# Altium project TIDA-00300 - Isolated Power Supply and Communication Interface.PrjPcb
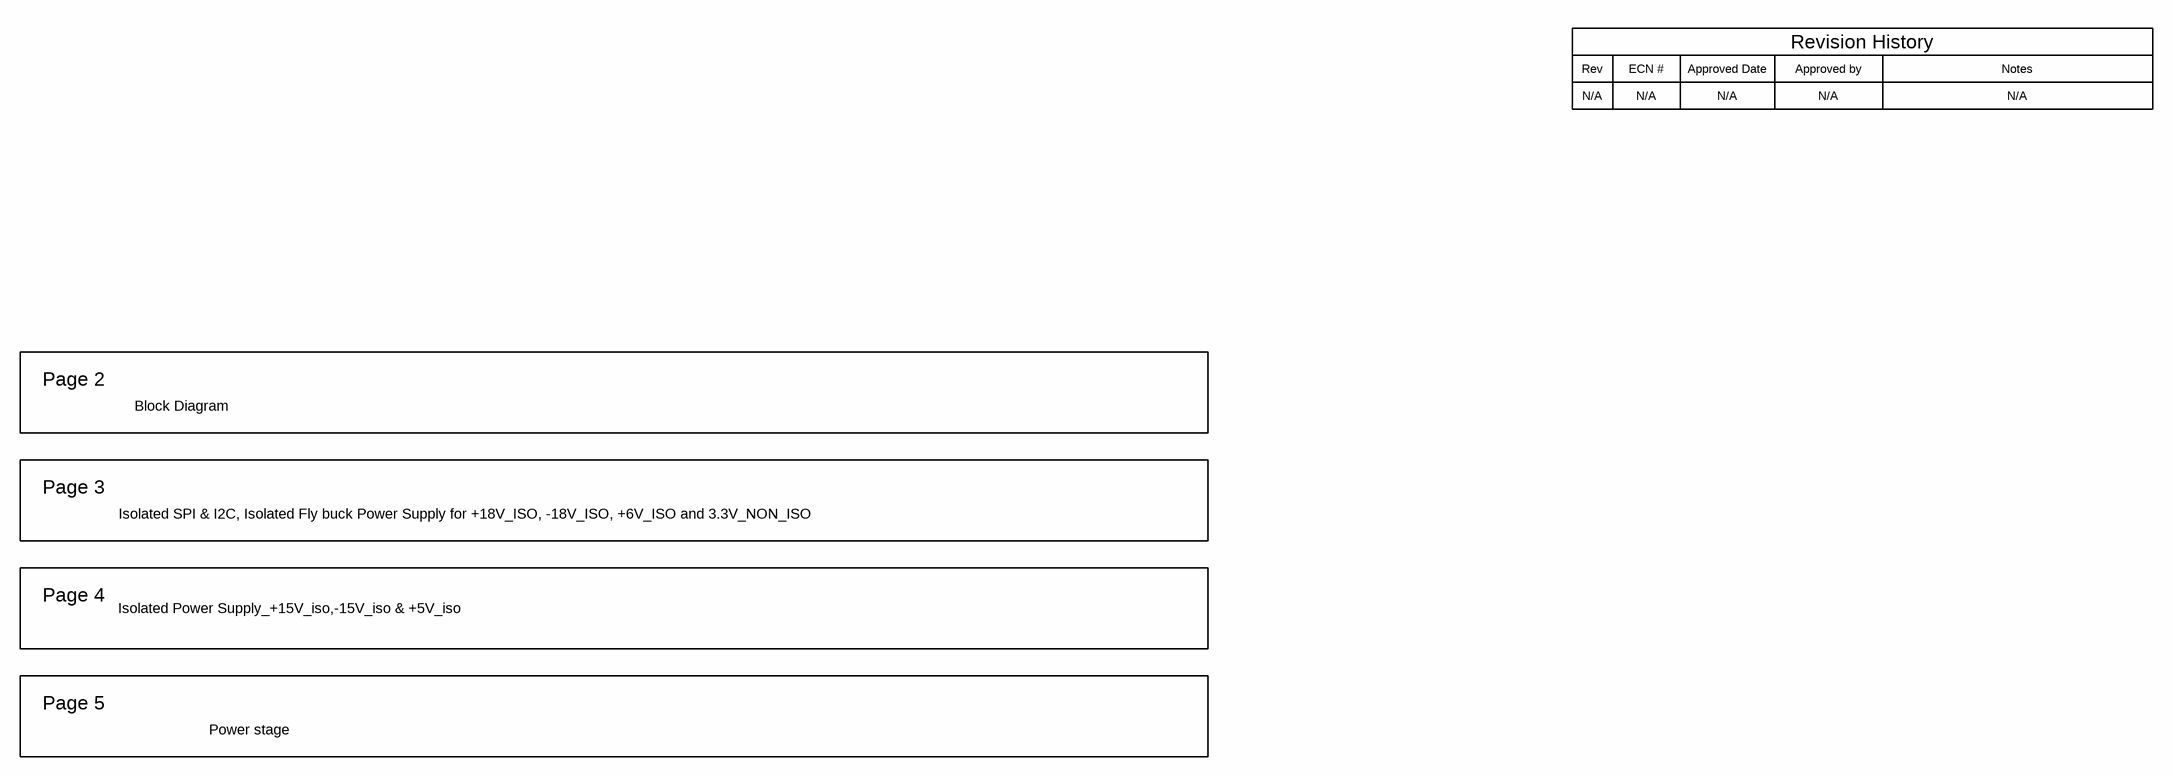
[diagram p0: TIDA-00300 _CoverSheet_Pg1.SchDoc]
CopyrightYear: 2019; PCB_Layout: Avinash N; PCB_Rev: E3; PRJ_Customer: Public Release; PRJ_Engineer: Sreenivasa; PRJ_Number: TIDA-00300; PRJ_Title: Isolated Power Supply and Communication Interface; SCH_Rev: E3; TechSupport: http://www.ti.com/support; TID: 00300
6 sheets, 197 parts. Net scope: flat (ports and power ports of the same name join across sheets).
Board file: TIDA-00300.PcbDoc
Sheets:
  TIDA-00300 _CoverSheet_Pg1.SchDoc
  TIDA-00300 _ Block Diagram_Pg2.SchDoc
  TIDA-00300_Isolated SPI, I2C & Fly buck Power Supply_Pg3 .SchDoc
  TIDA-00300_Isolated Power Supply +15V,-15V & +5V_Pg4 .SchDoc
  TIDA-00300_Power Stage_Pg5.SchDoc
  TIDA-00300_EVM_Hardware_Pg6.SchDoc

## Sheet TIDA-00300 _CoverSheet_Pg1.SchDoc: Coversheet
size 431 x 279 mm; Date: Not shown in title block; ApprovedBy: Not shown in title block; CheckedBy: Not shown in title block; Author: Not shown in title block; CompanyName: Not shown in title block; DrawnBy: Sreenivasa; Engineer: Not shown in title block; Organization: Not shown in title block; Address1: Not shown in title block; Address2: Not shown in title block; Address3: Not shown in title block; Address4: Not shown in title block; DocumentNumber: 1; Revision: Use project parameter SCH_Rev; SheetNumber: 1; SheetTotal: 6; PageSetup: Record=PageOptions¦CenterHorizontal=True¦CenterVertical=True¦PrintScale=1.00¦XCorrection=1.00¦YCorrection=1.00¦PrintKind=0¦BorderSize=5000000¦LeftOffset=0¦BottomOffset=0¦Orientation=2¦PaperLength=1000¦PaperWidth=1000¦Scale=100¦PaperSource=15¦PrintQuality=600¦MediaType=1¦DitherType=10¦PaperKind=Letter¦PrintScaleMode=1

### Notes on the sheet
- Rev
- N/A
- ECN #
- Approved Date
- Approved by
- Revision History
- Notes
- Page 2
- Block Diagram
- Page 3
- Isolated SPI & I2C, Isolated Fly buck Power Supply for +18V_ISO, -18V_ISO, +6V_ISO and 3.3V_NON_ISO
- Page 4
- Isolated Power Supply_+15V_iso,-15V_iso & +5V_iso
- Page 5
- Power stage

## Sheet TIDA-00300 _ Block Diagram_Pg2.SchDoc: Block Diagram
size 431 x 279 mm; Date: Not shown in title block; ApprovedBy: Not shown in title block; CheckedBy: Not shown in title block; Author: Not shown in title block; CompanyName: Not shown in title block; DrawnBy: Sreenivasa; Engineer: Sreenivasa; Organization: Not shown in title block; Address1: Not shown in title block; Address2: Not shown in title block; Address3: Not shown in title block; Address4: Not shown in title block; DocumentNumber: 1; Revision: Use project parameter SCH_Rev; SheetNumber: 2; SheetTotal: 6; PageSetup: Record=PageOptions¦CenterHorizontal=True¦CenterVertical=True¦PrintScale=1.00¦XCorrection=1.00¦YCorrection=1.00¦PrintKind=0¦BorderSize=5000000¦LeftOffset=0¦BottomOffset=0¦Orientation=2¦PaperLength=1000¦PaperWidth=1000¦Scale=100¦PaperSource=15¦PrintQuality=600¦MediaType=1¦DitherType=10¦PaperKind=Letter¦PrintScaleMode=1
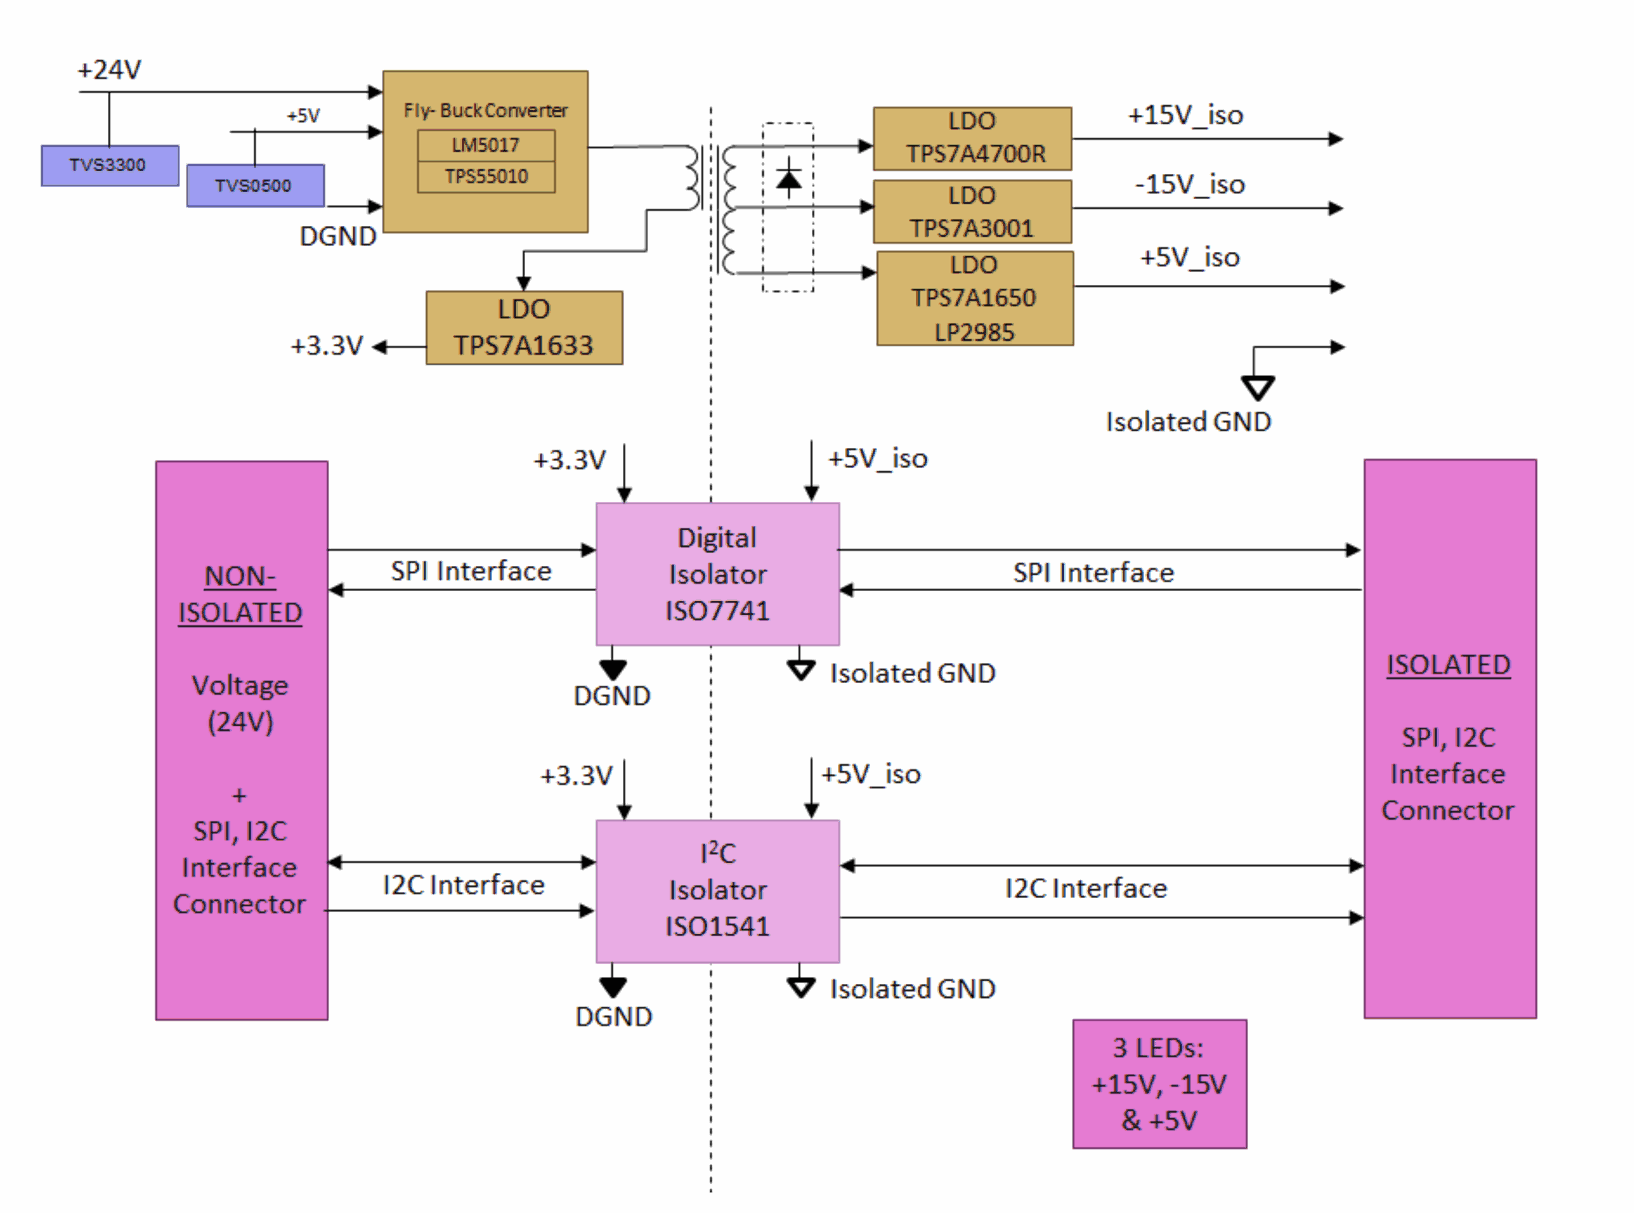
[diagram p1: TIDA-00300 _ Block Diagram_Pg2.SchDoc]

## Sheet TIDA-00300_Isolated SPI, I2C & Fly buck Power Supply_Pg3 .SchDoc
size 431 x 279 mm; Date: Not shown in title block; ApprovedBy: Not shown in title block; CheckedBy: Not shown in title block; Author: Not shown in title block; CompanyName: Not shown in title block; DrawnBy: Sreenivasa; Engineer: Not shown in title block; Organization: Not shown in title block; Address1: Not shown in title block; Address2: Not shown in title block; Address3: Not shown in title block; Address4: Not shown in title block; DocumentNumber: 1; Revision: Use project parameter SCH_Rev; SheetNumber: 3; SheetTotal: 6; PageSetup: Record=PageOptions¦CenterHorizontal=True¦CenterVertical=True¦PrintScale=0.62¦XCorrection=1.00¦YCorrection=1.00¦PrintKind=0¦BorderSize=5000000¦LeftOffset=0¦BottomOffset=0¦Orientation=2¦PaperLength=1000¦PaperWidth=1000¦Scale=100¦PaperSource=15¦PrintQuality=600¦MediaType=1¦DitherType=10¦PrintScaleMode=1¦PaperKind=Letter
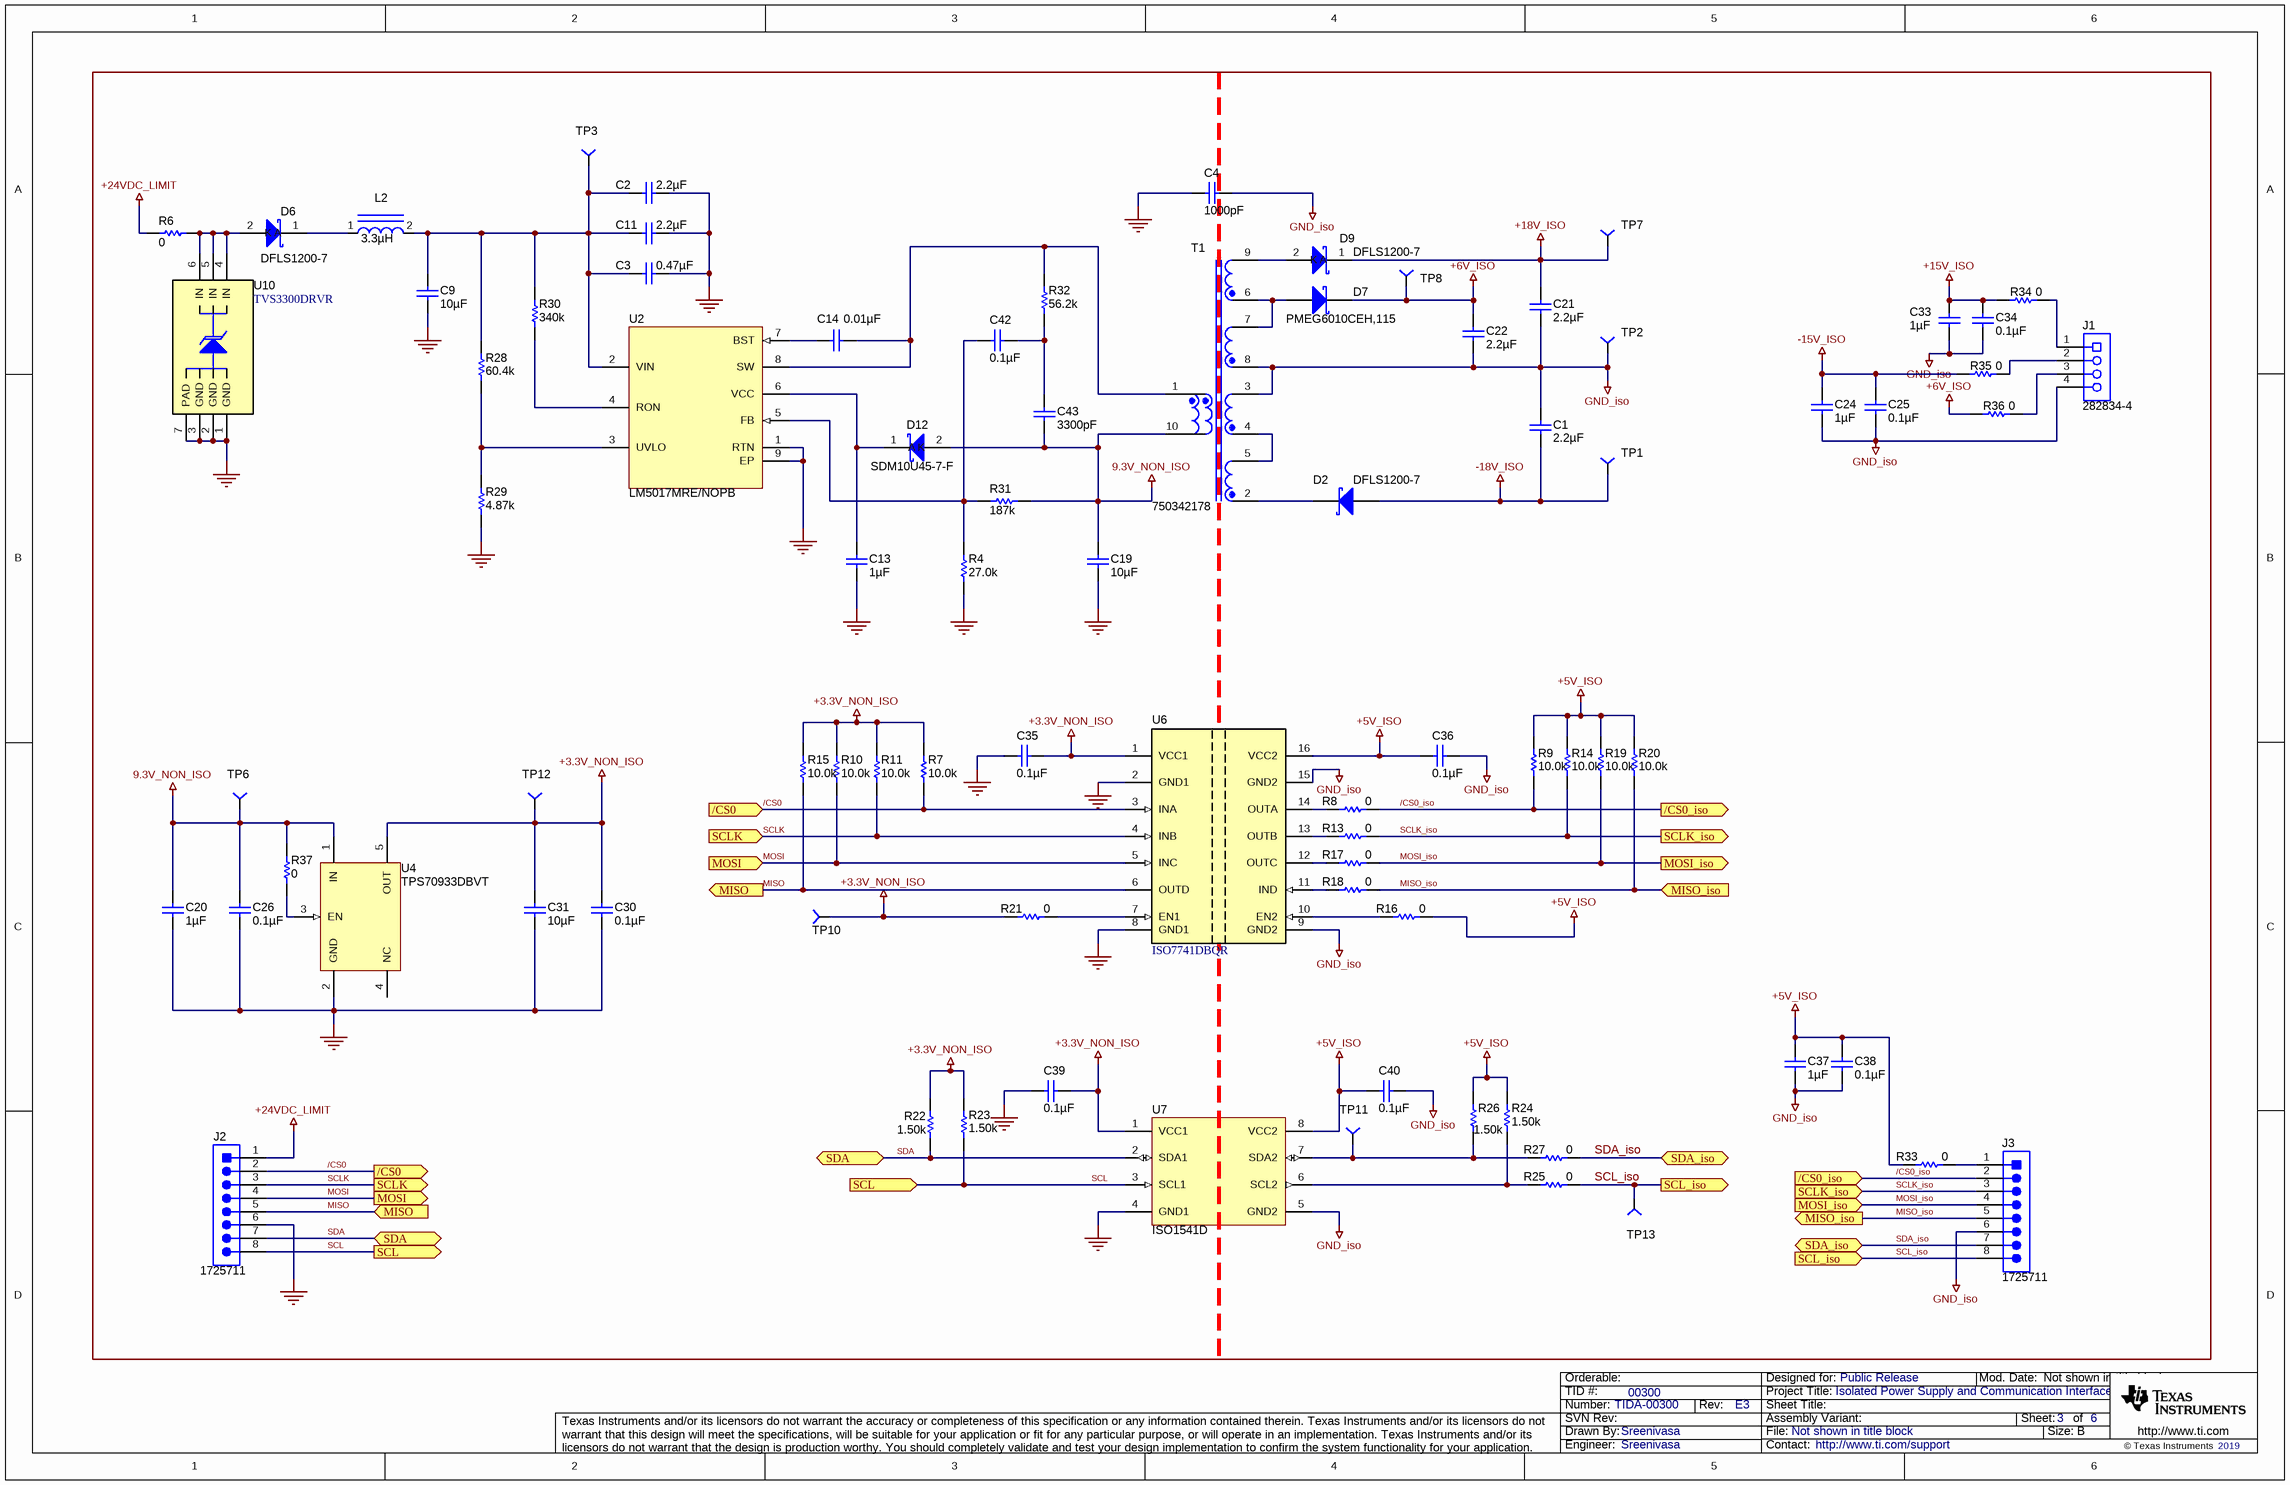
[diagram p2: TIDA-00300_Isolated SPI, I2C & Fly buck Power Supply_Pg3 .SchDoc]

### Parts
C1  ValueDisplayed: 2.2µF  [0805_HV]  (hidden comment: GRM21BR71E225KA73L)
C2  ValueDisplayed: 2.2µF  [1210]  (hidden comment: GRM32ER72A225KA35L)
C3  ValueDisplayed: 0.47µF  [1206]  (hidden comment: ESD61C474K4T2A-28)
C4  ValueDisplayed: 1000pF  [1812]  (hidden comment: 1812GC102KAT1A)
C9  ValueDisplayed: 10µF  [1210]  (hidden comment: GRM32ER71H106KA12L)
C11  ValueDisplayed: 2.2µF  [1210]  (hidden comment: GRM32ER72A225KA35L)
C13  ValueDisplayed: 1µF  [0603]  (hidden comment: C1608X5R1H105K080AB)
C14  ValueDisplayed: 0.01µF  [0603]  (hidden comment: 06031C103JAT2A)
C19  ValueDisplayed: 10µF  [1210]  (hidden comment: GMK325AB7106MM-T)
C20  ValueDisplayed: 1µF  [0805]  (hidden comment: 08055C105KAT2A)
C21  ValueDisplayed: 2.2µF  [0805_HV]  (hidden comment: GRM21BR71E225KA73L)
C22  ValueDisplayed: 2.2µF  [0805_HV]  (hidden comment: GRM21BR71E225KA73L)
C24  ValueDisplayed: 1µF  [0603]  (hidden comment: C1608X5R1H105K080AB)
C25  ValueDisplayed: 0.1µF  [0603]  (hidden comment: GRM188R72A104KA35D)
C26  ValueDisplayed: 0.1µF  [0603]  (hidden comment: C0603C104K5RACTU)
C30  ValueDisplayed: 0.1µF  [0603]  (hidden comment: C0603C104K5RACTU)
C31  ValueDisplayed: 10µF  [0805]  (hidden comment: 0805YD106MAT2A)
C33  ValueDisplayed: 1µF  [0603]  (hidden comment: C1608X5R1H105K080AB)
C34  ValueDisplayed: 0.1µF  [0603]  (hidden comment: GRM188R72A104KA35D)
C35  ValueDisplayed: 0.1µF  [0603]  (hidden comment: C0603C104K5RACTU)
C36  ValueDisplayed: 0.1µF  [0603]  (hidden comment: C0603C104K5RACTU)
C37  ValueDisplayed: 1µF  [0603]  (hidden comment: C1608X5R1H105K080AB)
C38  ValueDisplayed: 0.1µF  [0603]  (hidden comment: GRM188R72A104KA35D)
C39  ValueDisplayed: 0.1µF  [0603]  (hidden comment: C0603C104K5RACTU)
C40  ValueDisplayed: 0.1µF  [0603]  (hidden comment: C0603C104K5RACTU)
C42  ValueDisplayed: 0.1µF  [0603]  (hidden comment: GRM188R72A104KA35D)
C43  ValueDisplayed: 3300pF  [0603]  (hidden comment: 06031C332JAT2A)
D2  DFLS1200-7  [powerDI123]
D6  DFLS1200-7  [powerDI123]
D7  PMEG6010CEH,115  [SOD-123F]
D9  DFLS1200-7  [powerDI123]
D12  SDM10U45-7-F  [SOD-523]
J1  282834-4  [TEC_282834-4]
J2  1725711  [CONN_1725711]
J3  1725711  [CONN_1725711]
L2  3.3µH  [IND_B82422H]
R4  value 27.0k  [0603]  (hidden comment: RC0603FR-0727KL)
R6  value 0  [1206]  (hidden comment: RC1206JR-070RL)
R7  value 10.0k  [0603]  (hidden comment: CRCW060310K0FKEA)
R8  value 0  [0603]  (hidden comment: RC0603JR-070RL)
R9  value 10.0k  [0603]  (hidden comment: CRCW060310K0FKEA)
R10  value 10.0k  [0603]  (hidden comment: CRCW060310K0FKEA)
R11  value 10.0k  [0603]  (hidden comment: CRCW060310K0FKEA)
R13  value 0  [0603]  (hidden comment: RC0603JR-070RL)
R14  value 10.0k  [0603]  (hidden comment: CRCW060310K0FKEA)
R15  value 10.0k  [0603]  (hidden comment: CRCW060310K0FKEA)
R16  value 0  [0603]  (hidden comment: RC0603JR-070RL)
R17  value 0  [0603]  (hidden comment: RC0603JR-070RL)
R18  value 0  [0603]  (hidden comment: RC0603JR-070RL)
R19  value 10.0k  [0603]  (hidden comment: CRCW060310K0FKEA)
R20  value 10.0k  [0603]  (hidden comment: CRCW060310K0FKEA)
R21  value 0  [0603]  (hidden comment: RC0603JR-070RL)
R22  value 1.50k  [0603]  (hidden comment: CRCW06031K50FKEA)
R23  value 1.50k  [0603]  (hidden comment: CRCW06031K50FKEA)
R24  value 1.50k  [0603]  (hidden comment: CRCW06031K50FKEA)
R25  value 0  [0603]  (hidden comment: RC0603JR-070RL)
R26  value 1.50k  [0603]  (hidden comment: CRCW06031K50FKEA)
R27  value 0  [0603]  (hidden comment: RC0603JR-070RL)
R28  value 60.4k  [0603]  (hidden comment: ERA-3AEB6042V)
R29  value 4.87k  [0603]  (hidden comment: RC0603FR-074K87L)
R30  value 340k  [0603]  (hidden comment: CRCW0603340KFKEA)
R31  value 187k  [0603]  (hidden comment: ERA-3AEB1873V)
R32  value 56.2k  [0603]  (hidden comment: ERA-3AEB5622V)
R33  value 0  [1206]  (hidden comment: RC1206JR-070RL)
R34  value 0  [1206]  (hidden comment: RC1206JR-070RL)
R35  value 0  [1206]  (hidden comment: RC1206JR-070RL)
R36  value 0  [1206]  (hidden comment: RC1206JR-070RL)
R37  value 0  [0603]  (hidden comment: RC0603JR-070RL)
T1  750342178  [WURTH_750313995]
TP1  TP1_PD40_D0.5_S50  [TP1_PD40_D0.5_S50]  (value not drawn)
TP2  TP1_PD40_D0.5_S50  [TP1_PD40_D0.5_S50]  (value not drawn)
TP3  TP1_PD40_D0.5_S50  [TP1_PD40_D0.5_S50]  (value not drawn)
TP6  TP1_PD40_D0.5_S50  [TP1_PD40_D0.5_S50]  (value not drawn)
TP7  TP1_PD40_D0.5_S50  [TP1_PD40_D0.5_S50]  (value not drawn)
TP8  TP1_PD40_D0.5_S50  [TP1_PD40_D0.5_S50]  (value not drawn)
TP10  TP1_PD40_D0.5_S50  [TP1_PD40_D0.5_S50]  (value not drawn)
TP11  TP1_PD40_D0.5_S50  [TP1_PD40_D0.5_S50]  (value not drawn)
TP12  TP1_PD40_D0.5_S50  [TP1_PD40_D0.5_S50]  (value not drawn)
TP13  TP1_PD40_D0.5_S50  [TP1_PD40_D0.5_S50]  (value not drawn)
U2  LM5017MRE/NOPB  [DDA0008B_N]
U4  TPS70933DBVT  [DBV0005A_N]
U6  ISO7741DBQR  [DBQ0016A_N]
U7  ISO1541D  [D0008A_N]
U10  TVS3300DRVR  [DRV0006A]

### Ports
/CS0 (in), /CS0 (out), /CS0_iso (in), /CS0_iso (out), MISO (in), MISO (out), MISO_iso (in), MISO_iso (out), MOSI (in), MOSI (out), MOSI_iso (in), MOSI_iso (out), SCL (in), SCL (out), SCL_iso (in), SCL_iso (out), SCLK (in), SCLK (out), SCLK_iso (in), SCLK_iso (out), SDA (bidir), SDA_iso (bidir)

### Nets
9.3V_NON_ISO: C19.1 C20.1 C26.1 C43.2 D12.2(A) R31.2 R37.2 T1.10 TP6.1 U4.1(IN)
+3.3V_NON_ISO: C30.1 C31.1 C35.2 C39.2 R7.2 R10.2 R11.2 R15.2 R21.1 R22.2 R23.2 TP10.1 TP12.1 U4.5(OUT) U6.1(VCC1) U7.1(VCC1)
+5V_ISO: C36.1 C37.1 C38.2 C40.1 R9.2 R14.2 R16.2 R19.2 R20.2 R24.2 R26.2 R33.1 U6.16(VCC2) U7.8(VCC2)
+6V_ISO: C22.1 D7.1(K) R36.1 TP8.1
+15V_ISO: C33.2 C34.2 R34.1
+18V_ISO: C21.1 D9.1(K) TP7.1
+24VDC_LIMIT: J2.1 R6.2
-15V_ISO: C24.1 C25.2 R35.1
-18V_ISO: C1.2 D2.2(A) TP1.1
GND: C2.1 C3.1 C4.2 C9.2 C11.1 C13.2 C19.2 C20.2 C26.2 C30.2 C31.2 C35.1 C39.1 J2.6 R4.1 R29.1 U2.1(RTN) U2.9(EP) U4.2(GND) U6.2(GND1) U6.8(GND1) U7.4(GND1) U10.1(GND) U10.2(GND) U10.3(GND) U10.7(PAD)
GND_iso: C1.1 C4.1 C21.2 C22.2 C24.2 C25.1 C33.1 C34.1 C36.2 C37.2 C38.1 C40.2 J1.4 J3.6 T1.3 T1.8 TP2.1 U6.9(GND2) U6.15(GND2) U7.5(GND2)
/CS0: J2.2 R7.1 U6.3(INA) ; port /CS0
/CS0_iso: J3.2 R8.2 R9.1 ; port /CS0_iso
MISO: J2.5 R15.1 U6.6(OUTD) ; port MISO
MISO_iso: J3.5 R18.2 R20.1 ; port MISO_iso
MOSI: J2.4 R10.1 U6.5(INC) ; port MOSI
MOSI_iso: J3.4 R17.2 R19.1 ; port MOSI_iso
SCL: J2.8 R23.1 U7.3(SCL1) ; port SCL
SCL_iso: J3.8 R25.2 TP13.1 ; port SCL_iso
SCLK: J2.3 R11.1 U6.4(INB) ; port SCLK
SCLK_iso: J3.3 R13.2 R14.1 ; port SCLK_iso
SDA: J2.7 R22.1 U7.2(SDA1) ; port SDA
SDA_iso: J3.7 R27.2 ; port SDA_iso
NetC2_2: C2.2 C3.2 C9.1 C11.2 L2.2 R28.2 R30.2 TP3.1 U2.2(VIN)
NetC13_1: C13.1 D12.1(K) U2.6(VCC)
NetC14_1: C14.1 U2.7(BST)
NetC14_2: C14.2 R32.2 T1.1 U2.8(SW)
NetC42_1: C42.1 C43.1 R32.1
NetC42_2: C42.2 R4.2 R31.1 U2.5(FB)
NetD2_1: D2.1(K) T1.2
NetD6_1: D6.1(K) L2.1
NetD6_2: D6.2(A) R6.1 U10.4(IN) U10.5(IN) U10.6(IN)
NetD7_2: D7.2(A) T1.6 T1.7
NetD9_2: D9.2(A) T1.9
NetJ1_1: J1.1 R34.2
NetJ1_2: J1.2 R35.2
NetJ1_3: J1.3 R36.2
NetJ3_1: J3.1 R33.2
NetR8_1: R8.1 U6.14(OUTA)
NetR13_1: R13.1 U6.13(OUTB)
NetR16_1: R16.1 U6.10(EN2)
NetR17_1: R17.1 U6.12(OUTC)
NetR18_1: R18.1 U6.11(IND)
NetR21_2: R21.2 U6.7(EN1)
NetR24_1: R24.1 R25.1 U7.6(SCL2)
NetR26_1: R26.1 R27.1 TP11.1 U7.7(SDA2)
NetR28_1: R28.1 R29.2 U2.3(UVLO)
NetR30_1: R30.1 U2.4(RON)
NetR37_1: R37.1 U4.3(EN)
NetT1_4: T1.4 T1.5

Not connected (* = marked no-connect by the designer): U4 4(NC)

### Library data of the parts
C1 C21 C22 = GRM21BR71E225KA73L: CAP, CERM, 2.2uF, 25V, +/-10%, X7R, 0805; Manufacturer: MuRata; Polarized: N; CompType: Capacitor; U/M: EA; Cap_F: 0.0000022; Tolerance_%: 10; ESR_Ohm: 0.005; Value1: 0.005 ohm; VDC_V: 25; TaMin_C: -55; TaMax_C: 125; Cap_Case: 0805
C2 C11 = GRM32ER72A225KA35L: CAP, CERM, 2.2uF, 100V, +/-10%, X7R, 1210; Manufacturer: MuRata; Polarized: N; CompType: Capacitor; U/M: EA; Cap_F: 0.0000022; Tolerance_%: 10; ESR_Ohm: 0.007; Value1: 0.007 ohm; VDC_V: 100; IRMS_A: 4.4; TaMin_C: -55; TaMax_C: 125
C3 = GRM31MR72A474KA35L: CAP, CERM, 0.47uF, 100V, +/-10%, X7R, 1206; Manufacturer: AVX Corporation; Polarized: N; CompType: Capacitor; U/M: EA; Cap_F: 0.00000047; Tolerance_%: 10; Value1: Unknown; VDC_V: 100; TaMin_C: -55; TaMax_C: 125
C4 = 1812GC102KA1: CAP, CERM, 1000pF, 2000V, +/-10%, X7R, 1812; Manufacturer: AVX; Polarized: N; CompType: Capacitor; U/M: EA; Cap_F: 0.000000001; Tolerance_%: 10; Value1: Unknown; VDC_V: 2000; TaMin_C: -55; TaMax_C: 125
C9 = GRM32ER71H106KA12L: CAP, CERM, 10uF, 50V, +/-10%, X7R, 1210; Manufacturer: MuRata; Polarized: N; CompType: Capacitor; U/M: EA; Cap_F: 0.00001; Tolerance_%: 10; Value1: Unknown; VDC_V: 50; TaMin_C: -55; TaMax_C: 125
C13 C24 C33 C37 = GRM188R61H105KAALD: CAP, CERM, 1uF, 50V, +/-10%, X5R, 0603; Manufacturer: TDK Corporation; Polarized: N; CompType: Capacitor; U/M: EA; Cap_F: 0.000001; Tolerance_%: 10; Value1: Unknown; VDC_V: 50; TaMin_C: -55; TaMax_C: 85
C14 = 06031C103JAT2A: CAP, CERM, 0.01uF, 100V, +/-5%, X7R, 0603; Manufacturer: AVX; Polarized: N; CompType: Capacitor; U/M: EA; Cap_F: 0.00000001; Tolerance_%: 5; ESR_Ohm: 0.098; Value1: 0.098 ohm; VDC_V: 100; TaMin_C: -55; TaMax_C: 125
C19 = GMK325AB7106MM-T: CAP, CERM, 10uF, 35V, +/-20%, X7R, 1210; Manufacturer: Taiyo Yuden; Polarized: N; CompType: Capacitor; U/M: EA; Cap_F: 0.00001; Tolerance_%: 20; Value1: Unknown; VDC_V: 35; TaMin_C: -55; TaMax_C: 125
C20 = 08055C105KAT2A: CAP, CERM, 1uF, 50V, +/-10%, X7R, 0805; Manufacturer: AVX; Polarized: N; CompType: Capacitor; U/M: EA; Cap_F: 0.000001; Tolerance_%: 10; Value1: Unknown; VDC_V: 50; TaMin_C: -55; TaMax_C: 125
C25 C34 C38 C42 = GRM188R72A104KA35D: CAP, CERM, 0.1uF, 100V, +/-10%, X7R, 0603; Manufacturer: MuRata; Polarized: N; CompType: Capacitor; U/M: EA; Cap_F: 0.0000001; Tolerance_%: 10; Value1: Unknown; VDC_V: 100; TaMin_C: -55; TaMax_C: 125
C26 C30 C35 C36 C39 C40 = C0603C104K5RACTU: CAP, CERM, 0.1uF, 50V, +/-10%, X7R, 0603; Manufacturer: Kemet; Polarized: N; CompType: Capacitor; U/M: EA; Cap_F: 0.0000001; Tolerance_%: 10; Value1: Unknown; VDC_V: 50; TaMin_C: -55; TaMax_C: 125
C31 = 0805YD106MAT2A: CAP, CERM, 10uF, 16V, +/-20%, X5R, 0805; Manufacturer: AVX; Polarized: N; CompType: Capacitor; U/M: EA; Cap_F: 0.00001; Tolerance_%: 20; Value1: Unknown; VDC_V: 16; TaMin_C: -55; TaMax_C: 85
C43 = 06031C332JAT2A: CAP, CERM, 3300pF, 100V, +/-5%, X7R, 0603; Manufacturer: AVX; Polarized: N; CompType: Capacitor; U/M: EA; Cap_F: 0.0000000033; Tolerance_%: 5; ESR_Ohm: 0.159; Value1: 0.159 ohm; VDC_V: 100; TaMin_C: -55; TaMax_C: 125
D2 D6 D9 = DFLS1200-7: Diode, Schottky, 200V, 1A, PowerDI123; Manufacturer: Diodes Inc.; U/M: EA; Vf_V: 0.85; Value2: 0.85V; Io_A: 1; Vr_V: 200; TJmax_C: 175; RJC_CperW: 7
D7 = PMEG6010CEH,115: Diode, Schottky, 60V, 1A, SOD-123F; Manufacturer: NXP Semiconductor; U/M: EA; Vf_V: 0.57; Value2: 0.57V; Io_A: 1; Vr_V: 60; TJmax_C: 150
D12 = SDM10U45-7-F: Diode, Schottky, 45V, 0.1A, SOD-523; Manufacturer: Diodes Inc.; U/M: EA; Vf_V: 0.58; Value2: 0.58V; Io_A: 0.1; Vr_V: 45; TJmax_C: 125
J1 = 282834-4: Receptacle, 100mil, 4X1 TH; Manufacturer: TE Connectivity; SymbolCreator: a0411947; U/M: EA
J2 J3 = 1725711: Terminal Block, 8x1, 2.54 mm, TH; Manufacturer: Phoenix Contact; SymbolCreator: a0411947; U/M: EA
L2 = IND_ELJEA_SERIES: Inductor, Chip, ±10%; Manufacturer: EPCOS INC.; PartNumber: B82422H1332K; Area: 28000
R4 = RC0603FR-0727KL: RES, 27.0k ohm, 1%, 0.1W, 0603; Manufacturer: Yageo America; CompType: Resistor; Res_ohm: 27000; Value_Code: 27k0; Tolerance_%: 1; Power_W: 0.1; VDC_V: 150; TempCo: 200 ppm/C; U/M: EA
R6 = RC0402JR-070RL: RES, 0 ohm,0.1W, 1206; Manufacturer: Yageo America; CompType: Resistor; Value_Code: 0000; Tolerance_%: 5; Power_W: 0.1; VDC_V: 50; TempCo: 200 ppm/C; EIA_Code: E24; U/M: EA
R7 R9-R11 R14 R15 R19 R20 = RG1608P-103-B-T5: RES, 10.0k ohm, 1%, 0.1W, 0603; Manufacturer: Vishay Dale; CompType: Resistor; Res_ohm: 10000; Value_Code: 10k0; Tolerance_%: 1; Power_W: 0.1; VDC_V: 75; TempCo: 25 ppm/C; EIA_Code: E192; U/M: EA
R8 R13 R16-R18 R21 R25 R27 R37 = RC0402JR-070RL: RES, 0 ohm,5%, 0.1W, 0603; Manufacturer: Yageo America; CompType: Resistor; Value_Code: 0000; Tolerance_%: 5; Power_W: 0.1; VDC_V: 50; TempCo: 200 ppm/C; EIA_Code: E24; U/M: EA
R22-R24 R26 = CRCW06031K50FKEA: RES, 1.50k ohm, 1%, 0.1W, 0603; Manufacturer: Vishay-Dale; CompType: Resistor; Res_ohm: 1500; Value_Code: 1k50; Tolerance_%: 1; Power_W: 0.1; VDC_V: 75; TempCo: 100 ppm/C; EIA_Code: E96; U/M: EA
R28 = RT0603BRD0760K4L: RES, 60.4k ohm, 0.1%, 0.1W, 0603; Manufacturer: Panasonic Electronic Components; CompType: Resistor; Res_ohm: 60400; Value_Code: 60k4; Tolerance_%: 0.1; VDC_V: 75; TempCo: 25 ppm/C; EIA_Code: E192; U/M: EA
R29 = RC0603FR-074K87L: RES, 4.87k ohm, 1%, 0.1W, 0603; Manufacturer: Yageo America; CompType: Resistor; Res_ohm: 4870; Value_Code: 4k87; Tolerance_%: 1; Power_W: 0.1; VDC_V: 150; TempCo: 200 ppm/C; EIA_Code: E96; U/M: EA
R30 = RT0603BRD07340KL: RES, 340k ohm,1%, 0.1W, 0603; Manufacturer: Vishay Dale; CompType: Resistor; Res_ohm: 340000; Tolerance_%: 0.1; VDC_V: 75; TempCo: 25 ppm/C; EIA_Code: E192; U/M: EA
R31 = RT0603BRD07189KL: RES 187K OHM 1/10W .1% 0603 SMD; Manufacturer: Panasonic Electronic Components; CompType: Resistor; Res_ohm: 189000; Value_Code: 189k; Tolerance_%: 0.1; Value1: 0.1%; Value2: 0.1W; VDC_V: 75; TempCo: 25 ppm/C; EIA_Code: E192; U/M: EA
R32 = RT0603BRD0756K2L: RES, 56.2k ohm, 0.1%, 0.1W, 0603; Manufacturer: Panasonic Electronic Components; CompType: Resistor; Res_ohm: 56200; Value_Code: 56k2; Tolerance_%: 0.1; VDC_V: 75; TempCo: 25 ppm/C; EIA_Code: E192; U/M: EA
R33-R36 = RC0402JR-070RL: RES, 0 ohm,5%, 0.25W, 1206; Manufacturer: Yageo America; CompType: Resistor; Value_Code: 0000; Tolerance_%: 5; Power_W: 0.1; Value2: 0.125W; VDC_V: 50; TempCo: 200 ppm/C; EIA_Code: E24; U/M: EA
T1 = 750313995: Transformer, 50uH, SMT; Manufacturer: Wurth Elektronik eiSos; SymbolCreator: a0411947; DCR_Ohm: 0.11; LeakageL: 0.130uH; U/M: EA
TP1-TP3 TP6-TP8 TP10-TP13 = TP-040_RND: Test Point 40mil pad 20mil drill; Manufacturer: STD; Value: STD
U2 = LM5017MRE/NOPB: 100V, 600mA Constant On-Time Synchronous Buck Regulator, DDA0008B; Alternate Manufacturer: None; Manufacturer: Texas Instruments; SymbolCreator: a0412235; CompType: IC; U/M: EA
U4 = TPS70933DBVT: IC REG LDO 3.3V 0.15A SOT23-5; Alternate Manufacturer: None; Manufacturer: Texas Instruments; SymbolCreator: a0411947; U/M: EA
U6 = CMP-0013040-1: High Speed, Robust EMC Quad-Channel Digital Isolators, DBQ0016A (SSOP-16); Alternate Manufacturer: Texas Instruments; SizeAreaWB_mm2: 96; U/M: EA; SizeZ_mm: 1.75; SizeX_mm: 6; SizeY_mm: 10; SizeArea_mm2: 60; CompType: IC
U7 = ISO1541D: Low-Power Bidirectional I2C Isolators, D0008A; Alternate Manufacturer: None; Manufacturer: Texas Instruments; SymbolCreator: a0411947; CompType: IC; U/M: EA
U10 = CMP-0013424-7: 33-V Precision Surge Protection Clamp, DRV0006A (WSON-6); Manufacturer: Texas Instruments; Alternate PartNumber: TVS3300DRVT; SizeX_mm: 2; CompType: IC; SizeZ_mm: 0.8; SizeArea_mm2: 4; SizeAreaWB_mm2: 9; U/M: EA

## Sheet TIDA-00300_Isolated Power Supply +15V,-15V & +5V_Pg4 .SchDoc
size 431 x 279 mm; Date: Not shown in title block; ApprovedBy: Not shown in title block; CheckedBy: Not shown in title block; Author: Not shown in title block; CompanyName: Not shown in title block; DrawnBy: Sreenivasa; Engineer: Not shown in title block; Organization: Not shown in title block; Address1: Not shown in title block; Address2: Not shown in title block; Address3: Not shown in title block; Address4: Not shown in title block; DocumentNumber: 1; Revision: Use project parameter SCH_Rev; SheetNumber: 4; SheetTotal: 6; PageSetup: Record=PageOptions¦CenterHorizontal=True¦CenterVertical=True¦PrintScale=0.62¦XCorrection=1.00¦YCorrection=1.00¦PrintKind=0¦BorderSize=5000000¦LeftOffset=0¦BottomOffset=0¦Orientation=2¦PaperLength=1000¦PaperWidth=1000¦Scale=100¦PaperSource=15¦PrintQuality=600¦MediaType=1¦DitherType=10¦PrintScaleMode=1¦PaperKind=Letter
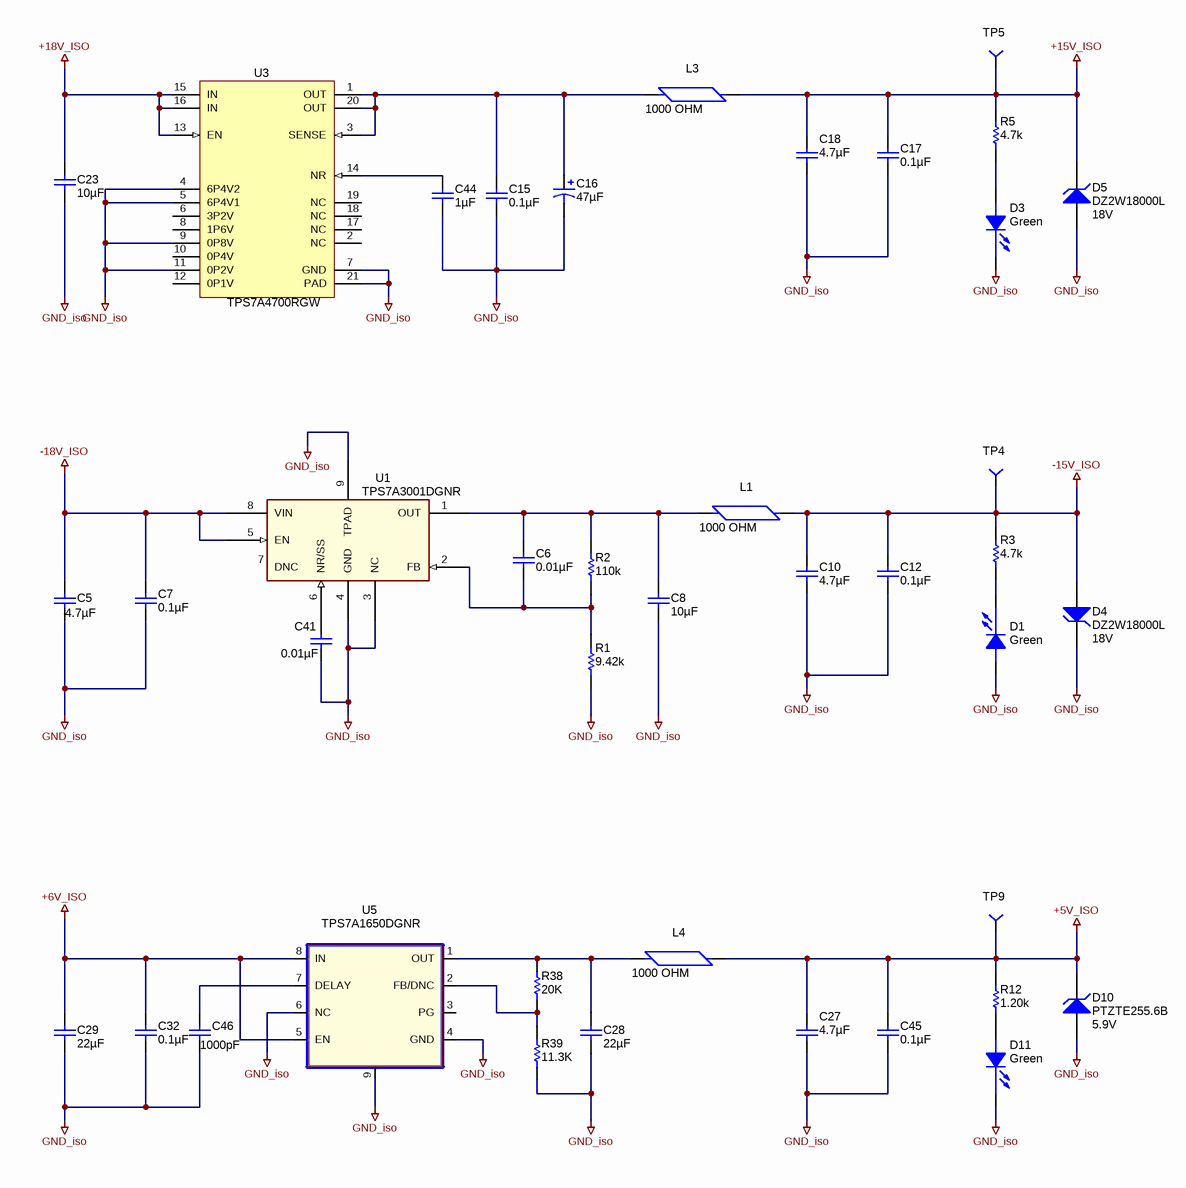
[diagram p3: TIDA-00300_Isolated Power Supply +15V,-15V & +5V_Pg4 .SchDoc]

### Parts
C5  ValueDisplayed: 4.7µF  [1206]  (hidden comment: GRM31CR71H475KA12L)
C6  ValueDisplayed: 0.01µF  [0603]  (hidden comment: 06031C103JAT2A)
C7  ValueDisplayed: 0.1µF  [0603]  (hidden comment: 06035C104KAT2A)
C8  ValueDisplayed: 10µF  [1206]  (hidden comment: GRM31CR71E106KA12L)
C10  ValueDisplayed: 4.7µF  [0805_HV]  (hidden comment: C2012X5R1H475K125AB)
C12  ValueDisplayed: 0.1µF  [0603]  (hidden comment: 06035C104KAT2A)
C15  ValueDisplayed: 0.1µF  [0603]  (hidden comment: 06035C104KAT2A)
C16  ValueDisplayed: 47µF  [7343-43]  (hidden comment: T495X476K035ATE300)
C17  ValueDisplayed: 0.1µF  [0603]  (hidden comment: 06035C104KAT2A)
C18  ValueDisplayed: 4.7µF  [0805_HV]  (hidden comment: C2012X5R1H475K125AB)
C23  ValueDisplayed: 10µF  [1210]  (hidden comment: GRM32ER71H106KA12L)
C27  ValueDisplayed: 4.7µF  [0805_HV]  (hidden comment: C2012X5R1H475K125AB)
C28  ValueDisplayed: 22µF  [0805_HV]  (hidden comment: GRM21BR61C226ME44)
C29  ValueDisplayed: 22µF  [0805_HV]  (hidden comment: GRM21BR61C226ME44)
C32  ValueDisplayed: 0.1µF  [0603]  (hidden comment: 06035C104KAT2A)
C41  ValueDisplayed: 0.01µF  [0603]  (hidden comment: 06031C103JAT2A)
C44  ValueDisplayed: 1µF  [0603]  (hidden comment: C1608X7R1E105K080AB)
C45  ValueDisplayed: 0.1µF  [0603]  (hidden comment: 06035C104KAT2A)
C46  ValueDisplayed: 1000pF  [0603]  (hidden comment: 06031C102JAT2A)
D1  value Green  [LED0603AA]  (hidden comment: LED_LG L29K-G2J1-24-Z)
D3  value Green  [LED0603AA]  (hidden comment: LED_LG L29K-G2J1-24-Z)
D4  DZ2W18000L  value 18V  [SOD-123]
D5  DZ2W18000L  value 18V  [SOD-123]
D10  PTZTE255.6B  value 5.9V  [DIO_SOD-106]
D11  value Green  [LED0603AA]  (hidden comment: LED_LG L29K-G2J1-24-Z)
L1  1000 OHM  [FB0603]
L3  1000 OHM  [FB0603]
L4  1000 OHM  [FB0603]
R1  value 9.42k  [0603]  (hidden comment: RNCF0603FKE9K42)
R2  value 110k  [0603]  (hidden comment: RG1608P-114-B-T5)
R3  value 4.7k  [0603]  (hidden comment: CRCW06034K70JNEA)
R5  value 4.7k  [0603]  (hidden comment: CRCW06034K70JNEA)
R12  value 1.20k  [0603]  (hidden comment: RG1608P-122-B-T5)
R38  value 20K  [0603]  (hidden comment: TNPW060320K0BEEA)
R39  value 11.3K  [0603]  (hidden comment: ERA-3AEB1132V)
TP4  TP-038  [TP1_PD40_D0.5_S50]  (value not drawn)
TP5  TP-038  [TP1_PD40_D0.5_S50]  (value not drawn)
TP9  TP-038  [TP1_PD40_D0.5_S50]  (value not drawn)
U1  TPS7A3001DGNR  [MSOP8(DGN)]
U3  TPS7A4700RGW  [RGW0020A]
U5  TPS7A1650DGNR  [DGN_8P]

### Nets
+5V_ISO: C27.1 C45.2 D10.1(K) L4.2 R12.2 TP9.1
+6V_ISO: C29.1 C32.2 U5.5(EN) U5.8(IN)
+15V_ISO: C17.2 C18.1 D5.1(K) L3.2 R5.1 TP5.1
+18V_ISO: C23.1 U3.13(EN) U3.15(IN) U3.16(IN)
-15V_ISO: C10.2 C12.2 D4.2(A) L1.2 R3.1 TP4.1
-18V_ISO: C5.1 C7.2 U1.5(EN) U1.8(VIN)
GND_iso: C5.2 C7.1 C8.2 C10.1 C12.1 C15.1 C16.2(-) C17.1 C18.2 C23.2 C27.2 C28.2 C29.2 C32.1 C41.2 C44.2 C45.1 C46.2 D1.2(A) D3.1(C) D4.1(K) D5.2(A) D10.2(A) D11.1(C) R1.2 R39.1 U1.3(NC) U1.4(GND) U1.9(TPAD) U3.4(6P4V2) U3.5(6P4V1) U3.7(GND) U3.9(0P8V) U3.11(0P2V) U3.21(PAD) U5.4(GND) U5.6(NC) U5.9
NetC6_1: C6.1 C8.1 L1.1 R2.2 U1.1(OUT)
NetC6_2: C6.2 R1.1 R2.1 U1.2(FB)
NetC15_2: C15.2 C16.1(+) L3.1 U3.1(OUT) U3.3(SENSE) U3.20(OUT)
NetC28_1: C28.1 L4.1 R38.2 U5.1(OUT)
NetC41_1: C41.1 U1.6(NR/SS)
NetC44_1: C44.1 U3.14(NR)
NetC46_1: C46.1 U5.7(DELAY)
NetD1_1: D1.1(C) R3.2
NetD3_2: D3.2(A) R5.2
NetD11_2: D11.2(A) R12.1
NetR38_1: R38.1 R39.2 U5.2(FB/DNC)

Not connected (* = marked no-connect by the designer): U1 7(DNC); U3 2(NC) 6(3P2V) 8(1P6V) 10(0P4V) 12(0P1V) 17(NC) 18(NC) 19(NC); U5 3(PG)

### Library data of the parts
C5 = GRM31CR71H475KA12L: CAP, CERM, 4.7uF, 50V, +/-10%, X7R, 1206; Manufacturer: MuRata; Polarized: N; CompType: Capacitor; U/M: EA; Cap_F: 0.0000047; Tolerance_%: 10; Value1: Unknown; VDC_V: 50; TaMin_C: -55; TaMax_C: 125; Cap_Case: 2220
C6 C41 = 06031C103JAT2A: as C14 on sheet TIDA-00300_Isolated SPI, I2C & Fly buck Power Supply_Pg3 
C7 C12 C15 C17 C32 C45 = 06035C104KAT2A: CAP, CERM, 0.1uF, 50V, +/-10%, X7R, 0603; Manufacturer: AVX; Polarized: N; CompType: Capacitor; U/M: EA; Cap_F: 0.0000001; Tolerance_%: 10; Value1: Unknown; VDC_V: 50; TaMin_C: -55; TaMax_C: 125
C8 = GRM31CR71E106KA12L: CAP, CERM, 10uF, 25V, +/-10%, X7R, 1206; Manufacturer: MuRata; Polarized: N; CompType: Capacitor; U/M: EA; Cap_F: 0.00001; Tolerance_%: 10; Value1: Unknown; VDC_V: 25; TaMin_C: -55; TaMax_C: 125; Cap_Case: 2220
C10 C18 C27 = C2012X5R1H475K125AB: CAP, CERM, 4.7uF, 50V, +/-10%, X5R, 0805; Manufacturer: TDK; Polarized: N; CompType: Capacitor; U/M: EA; Cap_F: 0.0000047; Tolerance_%: 10; Value1: Unknown; VDC_V: 50; TaMin_C: -55; TaMax_C: 85; Cap_Case: 0805
C16 = T495X476K035ATE300: CAP, TA, 47uF, 35V, +/-10%, 0.3 ohm, SMD; Manufacturer: Kemet; Polarized: Y; CompType: Capacitor; U/M: EA; Cap_F: 0.000047; Tolerance_%: 10; Value1: 0.3 ohm; VDC_V: 35; ESR_Ohm: 0.3; IRMS_A: 0.667; TaMin_C: -55; TaMax_C: 125; Cap_Case: X
C23 = GRM32ER71H106KA12L: as C9 on sheet TIDA-00300_Isolated SPI, I2C & Fly buck Power Supply_Pg3 
C28 C29 = GRM21BR61C226ME44: CAP, CERM, 22uF, 16V, +/-20%, X5R, 0805; Manufacturer: MuRata; Polarized: N; CompType: Capacitor; U/M: EA; Cap_F: 0.000022; Tolerance_%: 20; Value1: Unknown; VDC_V: 16; TaMin_C: -55; TaMax_C: 85; Cap_Case: 0805
C44 = C1608X7R1E105K080AB: CAP, CERM, 1uF, 25V, +/-10%, X7R, 0603; Manufacturer: TDK; Polarized: N; CompType: Capacitor; U/M: EA; Cap_F: 0.000001; Tolerance_%: 10; Value1: Unknown; VDC_V: 25; TaMin_C: -55; TaMax_C: 125
C46 = 06031C102JAT2A: CAP, CERM, 1000pF, 100V, +/-5%, X7R, 0603; Manufacturer: AVX; Polarized: N; CompType: Capacitor; U/M: EA; Cap_F: 0.000000001; Tolerance_%: 5; ESR_Ohm: 0.276; Value1: 0.276 ohm; VDC_V: 100; TaMin_C: -55; TaMax_C: 125
D1 D3 D11 = LED_LG L29K-G2J1-24-Z: LED SmartLED Green 570NM; Manufacturer: OSRAM; SymbolCreator: x0120606
D4 D5 = DZ2W18000L: Diode, Zener, 18V, 1W, SOD-123; Manufacturer: Panasonic
D10 = PTZTE255.6B: DIODE ZENER 5.9V 1W PMDS; Manufacturer: Rohm Semiconductor; U/M: EA; Vz_V: 5.9
L1 L3 L4 = MMZ1608B102C: FERRITE CHIP 1000 OHM 300MA 0603; Manufacturer: TDK Corporation; CompType: Ferrite Bead
R1 = CRCW04029K31FKED: RES, 9.42k ohm, 1%, 0.063W, 0603; Manufacturer: Vishay-Dale; CompType: Resistor; Value_Code: 9k42; Tolerance_%: 1; Power_W: 0.063; VDC_V: 50; TempCo: 100 ppm/C; EIA_Code: E96; U/M: EA
R2 = RG1608P-114-B-T5: RES, 110k ohm, 0.1%, 0.1W, 0603; Manufacturer: Susumu Co Ltd; CompType: Resistor; Res_ohm: 110000; Tolerance_%: 0.1; VDC_V: 75; TempCo: 25 ppm/C; EIA_Code: E192; U/M: EA
R3 R5 = CRCW06034K70JNEA: RES, 4.7k ohm, 5%, 0.1W, 0603; Manufacturer: Vishay-Dale; CompType: Resistor; Res_ohm: 4700; Value_Code: 4k70; Tolerance_%: 5; Power_W: 0.1; VDC_V: 75; TempCo: 200 ppm/C; EIA_Code: E24; U/M: EA
R12 = RG1608P-122-B-T5: RES, 1.20k ohm, 0.1%, 0.1W, 0603; Manufacturer: Susumu Co Ltd; CompType: Resistor; Res_ohm: 1200; Value_Code: 1k20; Tolerance_%: 0.1; VDC_V: 75; TempCo: 25 ppm/C; EIA_Code: E192; U/M: EA
R38 = RG1608P-122-B-T5: RES, 20K ohm, 0.1%, 0.1W, 0603; Manufacturer: Vishay Dale; CompType: Resistor; Tolerance_%: 0.1; VDC_V: 75; TempCo: 25 ppm/C; EIA_Code: E192; U/M: EA
R39 = RG1608P-122-B-T5: RES, 11.3K ohm, 0.1%, 0.1W, 0603; Manufacturer: panasonic electronic components; CompType: Resistor; Res_ohm: 1200; Value_Code: 11K3; Tolerance_%: 0.1; VDC_V: 75; TempCo: 25 ppm/C; EIA_Code: E192; U/M: EA
TP4 TP5 TP9 = TP-038: Test Point 40mil pad 20mil drill; Manufacturer: STD; Value: STD
U1 = TPS7A3001DGNR: -36V, -200mA, Ultralow-Noise, Negative Linear Regulator; Alternate Manufacturer: None; Manufacturer: Texas Instruments; CompType: IC; SymbolCreator: x0120606
U3 = TPS7A4700RGW: 36-V, 1-A, 4.17-µVRMS, RF LDO Voltage Regulator, RGW0020A; Alternate Manufacturer: None; Manufacturer: Texas Instruments; SymbolCreator: a0412235; CompType: IC; U/M: EA
U5 = TPS7A16XXDGN: IC, 60-V, 6-A IQ, 100-mA, LDO Voltage Regulator with Enable and Power-Good Functions; Manufacturer: TI; Alternate Manufacturer: None; Area: 35250

## Sheet TIDA-00300_Power Stage_Pg5.SchDoc
size 431 x 279 mm; Date: Not shown in title block; ApprovedBy: Not shown in title block; CheckedBy: Not shown in title block; Author: Not shown in title block; CompanyName: Not shown in title block; DrawnBy: Sreenivasa; Engineer: Not shown in title block; Organization: Not shown in title block; Address1: Not shown in title block; Address2: Not shown in title block; Address3: Not shown in title block; Address4: Not shown in title block; DocumentNumber: 1; Revision: Use project parameter SCH_Rev; SheetNumber: 5; SheetTotal: 6; PageSetup: Record=PageOptions¦CenterHorizontal=True¦CenterVertical=True¦PrintScale=0.62¦XCorrection=1.00¦YCorrection=1.00¦PrintKind=0¦BorderSize=5000000¦LeftOffset=0¦BottomOffset=0¦Orientation=2¦PaperLength=1000¦PaperWidth=1000¦Scale=100¦PaperSource=15¦PrintQuality=600¦MediaType=1¦DitherType=10¦PrintScaleMode=1¦PaperKind=Letter
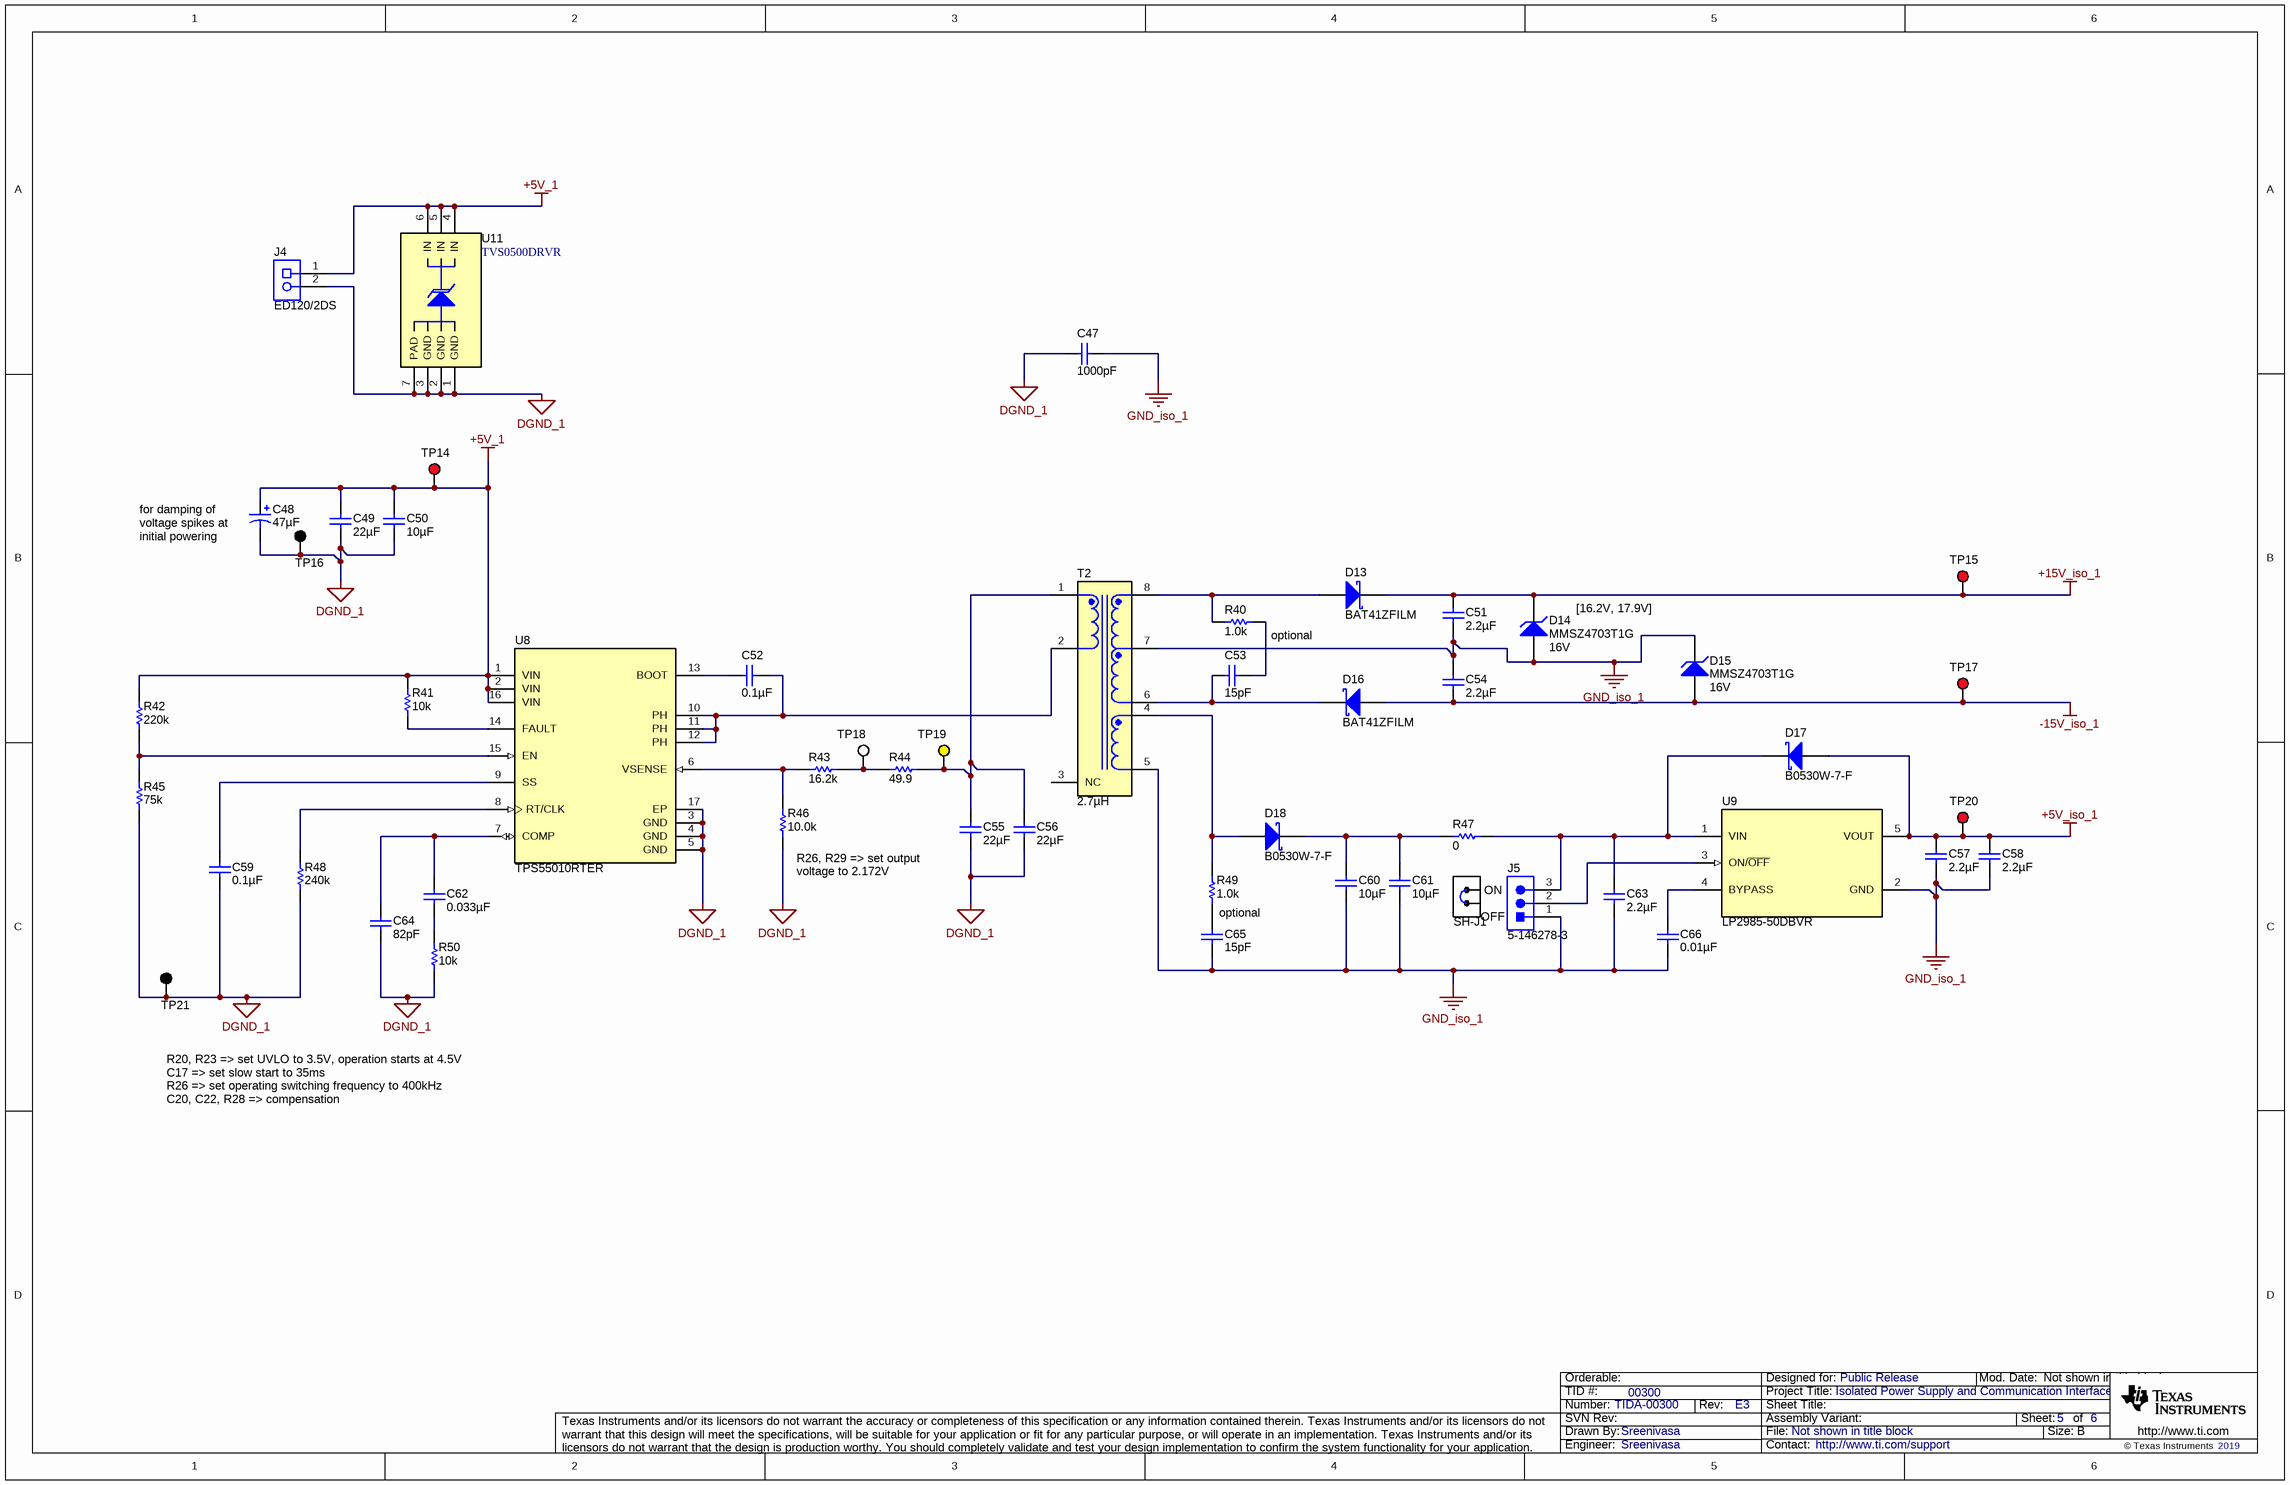
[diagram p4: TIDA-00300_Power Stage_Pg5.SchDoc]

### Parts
C47  ValueDisplayed: 1000pF  [1206_190]  (hidden comment: 202R18W102KV4E)
C48  ValueDisplayed: 47µF  [CAPPRD200W50D500H1100]  (hidden comment: ECA-1VM470)
C49  ValueDisplayed: 22µF  [1206_180]  (hidden comment: GRM31CR71A226KE15L)
C50  ValueDisplayed: 10µF  [0805_HV]  (hidden comment: C2012X7R1A106K125AC)
C51  ValueDisplayed: 2.2µF  [1206_180]  (hidden comment: GRM31CR71H225KA88L)
C52  ValueDisplayed: 0.1µF  [0603]  (hidden comment: GRM188R71H104KA93D)
C53  ValueDisplayed: 15pF  [0603]  (hidden comment: GRM1885C1H150JA01D)
C54  ValueDisplayed: 2.2µF  [1206_180]  (hidden comment: GRM31CR71H225KA88L)
C55  ValueDisplayed: 22µF  [1206_180]  (hidden comment: GRM31CR71A226KE15L)
C56  ValueDisplayed: 22µF  [1206_180]  (hidden comment: GRM31CR71A226KE15L)
C57  ValueDisplayed: 2.2µF  [0603]  (hidden comment: GRM188R71A225KE15D)
C58  ValueDisplayed: 2.2µF  [0603]  (hidden comment: GRM188R71A225KE15D)
C59  ValueDisplayed: 0.1µF  [0603]  (hidden comment: GRM188R71H104KA93D)
C60  ValueDisplayed: 10µF  [0805_HV]  (hidden comment: C2012X7R1A106K125AC)
C61  ValueDisplayed: 10µF  [0805_HV]  (hidden comment: C2012X7R1A106K125AC)
C62  ValueDisplayed: 0.033µF  [0603]  (hidden comment: GRM188R71H333KA61D)
C63  ValueDisplayed: 2.2µF  [0603]  (hidden comment: GRM188R71A225KE15D)
C64  ValueDisplayed: 82pF  [0603]  (hidden comment: GRM1885C1H820JA01D)
C65  ValueDisplayed: 15pF  [0603]  (hidden comment: GRM1885C1H150JA01D)
C66  ValueDisplayed: 0.01µF  [0603]  (hidden comment: 06031C103KAT2A)
D13  BAT41ZFILM  [SOD-123]
D14  MMSZ4703T1G  value 16V  [SOD-123]
D15  MMSZ4703T1G  value 16V  [SOD-123]
D16  BAT41ZFILM  [SOD-123]
D17  B0530W-7-F  [SOD-123]
D18  B0530W-7-F  [SOD-123]
J4  ED120/2DS  [CONN_ED120-2DS]
J5  5-146278-3  [TE_5-146278-3]
R40  ValueDisplayed: 1.0k  [0805_HV]  (hidden comment: ERJ-6GEYJ102V)
R41  ValueDisplayed: 10k  [0603]  (hidden comment: CRCW060310K0JNEA)
R42  ValueDisplayed: 220k  [0603]  (hidden comment: CRCW0603220KJNEA)
R43  ValueDisplayed: 16.2k  [0603]  (hidden comment: CRCW060316K2FKEA)
R44  ValueDisplayed: 49.9  [0603]  (hidden comment: CRCW060349R9FKEA)
R45  ValueDisplayed: 75k  [0603]  (hidden comment: CRCW060375K0JNEA)
R46  ValueDisplayed: 10.0k  [0603]  (hidden comment: CRCW060310K0FKEA)
R47  ValueDisplayed: 0  [0603]  (hidden comment: CRCW06030000Z0EA)
R48  ValueDisplayed: 240k  [0603]  (hidden comment: CRCW0603240KJNEA)
R49  ValueDisplayed: 1.0k  [0805_HV]  (hidden comment: ERJ-6GEYJ102V)
R50  ValueDisplayed: 10k  [0603]  (hidden comment: CRCW060310K0JNEA)
SH-J1  60900213421  [Wurth_60900213421]  (value not drawn)
T2  ValueDisplayed: 2.7µH  [Wurth_750316170]  (hidden comment: 750316449)
TP14  5000  [Keystone5000]  (value not drawn)
TP15  5000  [Keystone5000]  (value not drawn)
TP16  5001  [Keystone5001]  (value not drawn)
TP17  5000  [Keystone5000]  (value not drawn)
TP18  5002  [Keystone5002]  (value not drawn)
TP19  5004  [Keystone5004]  (value not drawn)
TP20  5000  [Keystone5000]  (value not drawn)
TP21  5001  [Keystone5001]  (value not drawn)
U8  TPS55010RTER  [RTE0016F]
U9  LP2985-50DBVR  [DBV0005A_N]
U11  TVS0500DRVR  [DRV0006A]

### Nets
+5V_1: C48.1(+) C49.1 C50.2 J4.1 R41.2 R42.2 TP14.1 U8.1(VIN) U8.2(VIN) U8.16(VIN) U11.4(IN) U11.5(IN) U11.6(IN)
+5V_iso_1: C57.1 C58.1 D17.2(A) TP20.1 U9.5(VOUT)
+15V_iso_1: C51.1 D13.1(K) D14.1(K) TP15.1
-15V_iso_1: C54.2 D15.2(A) D16.2(A) TP17.1
DGND_1: C47.2 C48.2(-) C49.2 C50.1 C55.2 C56.2 C59.2 C64.1 J4.2 R45.1 R46.1 R48.1 R50.1 TP16.1 TP21.1 U8.3(GND) U8.4(GND) U8.5(GND) U8.17(EP) U11.1(GND) U11.2(GND) U11.3(GND) U11.7(PAD)
GND_iso_1: C47.1 C51.2 C54.1 C57.2 C58.2 C60.2 C61.1 C63.2 C65.2 C66.2 D14.2(A) D15.1(K) J5.1 T2.5 T2.7 U9.2(GND)
NetC52_1: C52.1 T2.2 U8.10(PH) U8.11(PH) U8.12(PH)
NetC52_2: C52.2 U8.13(BOOT)
NetC53_1: C53.1 R40.1
NetC53_2: C53.2 D16.1(K) T2.6
NetC55_1: C55.1 C56.1 R44.2 T2.1 TP19.1
NetC59_1: C59.1 U8.9(SS)
NetC60_1: C60.1 C61.2 D18.1(K) R47.1
NetC62_1: C62.1 C64.2 U8.7(COMP)
NetC62_2: C62.2 R50.2
NetC63_1: C63.1 D17.1(K) J5.3 R47.2 U9.1(VIN)
NetC65_1: C65.1 R49.1
NetC66_1: C66.1 U9.4(BYPASS)
NetD13_2: D13.2(A) R40.2 T2.8
NetD18_2: D18.2(A) R49.2 T2.4
NetJ5_2: J5.2 U9.3(ON/~{OFF})
NetR41_1: R41.1 U8.14(FAULT)
NetR42_1: R42.1 R45.2 U8.15(EN)
NetR43_1: R43.1 R44.1 TP18.1
NetR43_2: R43.2 R46.2 U8.6(VSENSE)
NetR48_2: R48.2 U8.8(RT/CLK)

Not connected (* = marked no-connect by the designer): T2 3(NC)

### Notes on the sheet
- (near C48) for damping of voltage spikes at initial powering
- (near R40) optional
- [16.2V, 17.9V]
- (near R46) R26, R29 => set output voltage to 2.172V
- ON
- (near R49) optional
- OFF
- R20, R23 => set UVLO to 3.5V, operation starts at 4.5V
  C17 => set slow start to 35ms
  R26 => set operating switching frequency to 400kHz
  C20, C22, R28 => compensation

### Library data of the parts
C47 = 202R18W102KV4E: CAP, CERM, 1000 pF, 2000 V, +/- 10%, X7R, 1206_190; Manufacturer: Johanson Technology; Polarized: N; CompType: Capacitor; Value: 1000pF; U/M: EA; Cap_F: 0.000000001; Tolerance_%: 10; Value1: Unknown; VDC_V: 2000; Value2: 2000V; TaMin_C: -55; TaMax_C: 125; Cap_Case: 1206; AEC Category: Q200; SizeArea_mm2: 5.12; SizeAreaWB_mm2: 10.92; SizeX_mm: 3.2; SizeY_mm: 1.6; SizeZ_mm: 1.9
C48 = ECA-1VM470: CAP, AL, 47 µF, 35 V, +/- 20%, TH; Manufacturer: Panasonic; Polarized: Y; CompType: Capacitor; Value: 47uF; U/M: EA; Cap_F: 0.000047; Tolerance_%: 20; Value1: Unknown; VDC_V: 35; Value2: 35V; IRMS_A: 0.13; TaMin_C: -40; TaMax_C: 85; Cap_Case: RCAP, 5x11mm; AEC Category: Q200; AEC Qualified: N
C49 C55 C56 = GRM31CR71A226KE15L: CAP, CERM, 22 µF, 10 V, +/- 10%, X7R, 1206; Manufacturer: MuRata; Polarized: N; CompType: Capacitor; Value: 22uF; U/M: EA; Cap_F: 0.000022; Tolerance_%: 10; Value1: Unknown; Value2: 10V; TaMin_C: -55; TaMax_C: 125; Cap_Case: 1206; AEC Category: Q200; SizeArea_mm2: 5.12; SizeAreaWB_mm2: 10.92; SizeX_mm: 3.2; SizeY_mm: 1.6; SizeZ_mm: 1.8
C50 C60 C61 = C2012X7R1A106K125AC: CAP, CERM, 10 µF, 10 V, +/- 10%, X7R, 0805; Manufacturer: TDK; Polarized: N; CompType: Capacitor; Value: 10uF; U/M: EA; Cap_F: 0.00001; Tolerance_%: 10; ESR_ohm: 0.001063; Value1: 0.001063 ohm; Value2: 10V; IRMS_A: 6.32908; TaMin_C: -55; TaMax_C: 125; Cap_Case: 0805; AEC Category: Q200; SizeArea_mm2: 2.5; SizeAreaWB_mm2: 6.75; SizeX_mm: 2; SizeY_mm: 1.25; SizeZ_mm: 1.45
C51 C54 = GRM31CR71H225KA88L: CAP, CERM, 2.2 µF, 50 V, +/- 10%, X7R, 1206; Manufacturer: MuRata; Polarized: N; CompType: Capacitor; Value: 2.2uF; U/M: EA; Cap_F: 0.0000022; Tolerance_%: 10; Value1: Unknown; VDC_V: 50; Value2: 50V; TaMin_C: -55; TaMax_C: 125; Cap_Case: 1206; AEC Category: Q200; SizeArea_mm2: 5.12; SizeAreaWB_mm2: 10.92; SizeX_mm: 3.2; SizeY_mm: 1.6; SizeZ_mm: 1.8
C52 C59 = GRM188R71H104KA93D: CAP, CERM, 0.1 µF, 50 V, +/- 10%, X7R, 0603; Manufacturer: MuRata; Polarized: N; CompType: Capacitor; Value: 0.1uF; U/M: EA; Cap_F: 0.0000001; Tolerance_%: 10; Value1: Unknown; VDC_V: 50; Value2: 50V; TaMin_C: -55; TaMax_C: 125; SizeArea_mm2: 1.28; SizeAreaWB_mm2: 4.68; SizeX_mm: 1.6; SizeY_mm: 0.8; SizeZ_mm: 1; AEC Category: Q200
C53 C65 = GRM1885C1H150JA01D: CAP, CERM, 15 pF, 50 V, +/- 5%, C0G/NP0, 0603; Manufacturer: MuRata; Polarized: N; CompType: Capacitor; Value: 15pF; U/M: EA; Cap_F: 0.000000000015; Tolerance_%: 5; Value1: Unknown; VDC_V: 50; Value2: 50V; TaMin_C: -55; TaMax_C: 125; SizeArea_mm2: 1.28; SizeAreaWB_mm2: 4.68; SizeX_mm: 1.6; SizeY_mm: 0.8; SizeZ_mm: 1; AEC Category: Q200
C57 C58 C63 = GRM188R71A225KE15D: CAP, CERM, 2.2 µF, 10 V, +/- 10%, X7R, 0603; Manufacturer: MuRata; Polarized: N; CompType: Capacitor; Value: 2.2uF; U/M: EA; Cap_F: 0.0000022; Tolerance_%: 10; ESR_ohm: 0.009; Value1: 0.009 ohm; Value2: 10V; TaMin_C: -55; TaMax_C: 125; AEC Category: Q200; SizeArea_mm2: 1.28; SizeAreaWB_mm2: 4.68; SizeX_mm: 1.6; SizeY_mm: 0.8; SizeZ_mm: 1
C62 = GRM188R71H333KA61D: CAP, CERM, 0.033 µF, 50 V, +/- 10%, X7R, 0603; Manufacturer: MuRata; Polarized: N; CompType: Capacitor; Value: 0.033uF; U/M: EA; Cap_F: 0.000000033; Tolerance_%: 10; Value1: Unknown; VDC_V: 50; Value2: 50V; TaMin_C: -55; TaMax_C: 125; AEC Category: Q200; SizeArea_mm2: 1.28; SizeAreaWB_mm2: 4.68; SizeX_mm: 1.6; SizeY_mm: 0.8; SizeZ_mm: 1
C64 = GRM1885C1H820JA01D: CAP, CERM, 82 pF, 50 V, +/- 5%, C0G/NP0, 0603; Manufacturer: MuRata; Polarized: N; CompType: Capacitor; Value: 82pF; U/M: EA; Cap_F: 0.000000000082; Tolerance_%: 5; Value1: Unknown; VDC_V: 50; Value2: 50V; TaMin_C: -55; TaMax_C: 125; AEC Category: Q200; SizeArea_mm2: 1.28; SizeAreaWB_mm2: 4.68; SizeX_mm: 1.6; SizeY_mm: 0.8; SizeZ_mm: 1
C66 = 06031C103KAT2A: CAP, CERM, 0.01 µF, 100 V, +/- 10%, X7R, 0603; Manufacturer: AVX; Polarized: N; CompType: Capacitor; Value: 0.01uF; U/M: EA; Cap_F: 0.00000001; Tolerance_%: 10; ESR_ohm: 0.098; Value1: 0.098 ohm; VDC_V: 100; Value2: 100V; TaMin_C: -55; TaMax_C: 125; SizeArea_mm2: 1.28; SizeAreaWB_mm2: 4.68; SizeX_mm: 1.6; SizeY_mm: 0.8; SizeZ_mm: 1; AEC Category: Q200
D13 D16 = BAT41ZFILM: Diode, Schottky, 100 V, 0.2 A, SOD-123; Manufacturer: STMicroelectronics; U/M: EA; Vf_V: 1; Value: 100V; Value1: 0.2A; Value2: 1V; Io_A: 0.2; Vr_V: 100; TJmax_C: 150; SizeAreaWB_mm2: 13.095; SizeArea_mm2: 6.545; SizeX_mm: 3.85; SizeY_mm: 1.7; SizeZ_mm: 1.35; AEC Category: Q101
D14 D15 = MMSZ4703T1G: Diode, Zener, 16 V, 500 mW, SOD-123; Manufacturer: ON Semiconductor; SymbolCreator: a0412235; U/M: EA; Power_W: 0.5; Vz_V: 16; Value1: 0.5W; RJA_CperW: 340; AEC Category: Q101; SizeAreaWB_mm2: 13.095; SizeArea_mm2: 6.545; SizeX_mm: 3.85; SizeY_mm: 1.7; SizeZ_mm: 1.35
D17 D18 = B0530W-7-F: Diode, Schottky, 30 V, 0.5 A, SOD-123; Manufacturer: Diodes Inc.; U/M: EA; Vf_V: 0.43; Value: 30V; Value1: 0.5A; Value2: 0.43V; Io_A: 0.5; Vr_V: 30; TJmax_C: 125; AEC Category: Q101; SizeAreaWB_mm2: 13.095; SizeArea_mm2: 6.545; SizeX_mm: 3.85; SizeY_mm: 1.7; SizeZ_mm: 1.35
J4 = ED120/2DS: TERMINAL BLOCK 5.08MM VERT 2POS, TH; Manufacturer: On-Shore Technology; SymbolCreator: a0412235; U/M: EA
J5 = 5-146278-3: Header, 100mil, 3x1, Tin, TH; Manufacturer: TE Connectivity; SymbolCreator: a0799628
R40 R49 = ERJ-6GEYJ102V: RES, 1.0 k, 5%, 0.125 W, 0805; Manufacturer: Panasonic; CompType: Resistor; Value: 1.0k; Res_ohm: 1000; Value_Code: 1k00; Tolerance_%: 5; Power_W: 0.125; Value2: 0.125W; VDC_V: 150; TempCo: 200 ppm/C; EIA_Code: E24; U/M: EA; AEC Category: Q200; SizeArea_mm2: 2.5; SizeX_mm: 2; SizeY_mm: 1.25; SizeZ_mm: 1.45
R41 R50 = CRCW060310K0JNEA: RES, 10 k, 5%, 0.1 W, 0603; Manufacturer: Vishay-Dale; CompType: Resistor; Value: 10k; Res_ohm: 10000; Value_Code: 10k0; Tolerance_%: 5; Power_W: 0.1; Value2: 0.1W; VDC_V: 75; TempCo: 200 ppm/C; EIA_Code: E24; U/M: EA; AEC Category: Q200; SizeArea_mm2: 1.28; SizeX_mm: 1.6; SizeY_mm: 0.8; SizeZ_mm: 1
R42 = CRCW0603220KJNEA: RES, 220 k, 5%, 0.1 W, 0603; Manufacturer: Vishay-Dale; CompType: Resistor; Value: 220k; Res_ohm: 220000; Tolerance_%: 5; Power_W: 0.1; Value2: 0.1W; VDC_V: 75; TempCo: 200 ppm/C; EIA_Code: E24; U/M: EA; AEC Category: Q200; SizeArea_mm2: 1.28; SizeX_mm: 1.6; SizeY_mm: 0.8; SizeZ_mm: 1
R43 = CRCW060316K2FKEA: RES, 16.2 k, 1%, 0.1 W, 0603; Manufacturer: Vishay-Dale; CompType: Resistor; Value: 16.2k; Res_ohm: 16200; Value_Code: 16k2; Tolerance_%: 1; Power_W: 0.1; Value2: 0.1W; VDC_V: 75; TempCo: 100 ppm/C; EIA_Code: E96; U/M: EA; AEC Category: Q200; SizeArea_mm2: 1.28; SizeX_mm: 1.6; SizeY_mm: 0.8
R44 = CRCW060349R9FKEA: RES, 49.9, 1%, 0.1 W, 0603; Manufacturer: Vishay-Dale; CompType: Resistor; Value: 49.9; Value_Code: 49R9; Tolerance_%: 1; Power_W: 0.1; Value2: 0.1W; VDC_V: 75; TempCo: 100 ppm/C; SizeArea_mm2: 1.28; SizeX_mm: 1.6; SizeY_mm: 0.8; EIA_Code: E96; U/M: EA; AEC Category: Q200
R45 = CRCW060375K0JNEA: RES, 75 k, 5%, 0.1 W, 0603; Manufacturer: Vishay-Dale; CompType: Resistor; Value: 75k; Res_ohm: 75000; Value_Code: 75k0; Tolerance_%: 5; Power_W: 0.1; Value2: 0.1W; VDC_V: 75; TempCo: 200 ppm/C; SizeArea_mm2: 1.28; SizeX_mm: 1.6; SizeY_mm: 0.8; SizeZ_mm: 1; EIA_Code: E24; U/M: EA; AEC Category: Q200
R46 = CRCW060310K0FKEA: RES, 10.0 k, 1%, 0.1 W, 0603; Manufacturer: Vishay-Dale; CompType: Resistor; Value: 10.0k; Res_ohm: 10000; Value_Code: 10k0; Tolerance_%: 1; Power_W: 0.1; Value2: 0.1W; VDC_V: 75; TempCo: 100 ppm/C; EIA_Code: E96; U/M: EA; AEC Category: Q200; SizeArea_mm2: 1.28; SizeX_mm: 1.6; SizeY_mm: 0.8
R47 = CRCW06030000Z0EA: RES, 0, 5%, 0.1 W, 0603; Manufacturer: Vishay-Dale; CompType: Resistor; Value: 0; Value_Code: 0000; Tolerance_%: 5; Power_W: 0.1; Value2: 0.1W; VDC_V: 75; TempCo: 200 ppm/C; EIA_Code: E24; U/M: EA; AEC Category: Q200; SizeArea_mm2: 1.28; SizeX_mm: 1.6; SizeY_mm: 0.8; SizeZ_mm: 1
R48 = CRCW0603240KJNEA: RES, 240 k, 5%, 0.1 W, 0603; Manufacturer: Vishay-Dale; CompType: Resistor; Value: 240k; Res_ohm: 240000; Tolerance_%: 5; Power_W: 0.1; Value2: 0.1W; VDC_V: 75; TempCo: 200 ppm/C; EIA_Code: E24; U/M: EA; AEC Category: Q200; SizeArea_mm2: 1.28; SizeX_mm: 1.6; SizeY_mm: 0.8; SizeZ_mm: 1
SH-J1 = 60900213421: Shunt, 2.54mm, Gold, Black; Manufacturer: Wurth Elektronik
T2 = 750316449: Transformer, 2.7 uH, SMT; Manufacturer: Wurth Elektronik; SymbolCreator: Altium; Value: 2.7uH; Lp: 2.7; DCR_ohm: 0.015; LeakageL: 0.5; Ns1toNp: 7; Ns3toNp: 3; Rs1: 1.45; Rs3: 0.435
TP14 TP15 TP17 TP20 = 5000: Test Point, Miniature, Red, TH; Manufacturer: Keystone; CompType: Test Point Loop; ContactFinish: Silver
TP16 TP21 = 5001: Test Point, Miniature, Black, TH; Manufacturer: Keystone; CompType: Test Point Loop; ContactFinish: Silver
TP18 = 5002: Test Point, Miniature, White, TH; Manufacturer: Keystone; CompType: Test Point Loop; ContactFinish: Silver
TP19 = 5004: Test Point, Miniature, Yellow, TH; Manufacturer: Keystone; CompType: Test Point Loop; ContactFinish: Silver
U8 = TPS55010RTER: 2.95V To 6V Input, 2W, Isolated DC/DC Converter with Integrated FETs, RTE0016F (WQFN-16); Manufacturer: Texas Instruments; SymbolCreator: Altium; SizeArea_mm2: 9; SizeAreaWB_mm2: 16; SizeX_mm: 3; SizeZ_mm: 0.8; CompType: IC; U/M: EA
U9 = LP2985-50DBVR: 150-mA Low-noise Low-dropout Regulator With Shutdown, DBV0005A; Alternate PartNumber: LP2985-50DBVT; Manufacturer: Texas Instruments; SymbolCreator: Altium; CompType: IC; U/M: EA; SizeArea_mm2: 8.12; SizeAreaWB_mm2: 14.82; SizeX_mm: 2.8; SizeY_mm: 2.9; SizeZ_mm: 1.45
U11 = CMP-0077837-1: 5-V Precision Surge Protection Clamp, DRV0006A (WSON-6); Alternate Manufacturer: Texas Instruments; SizeAreaWB_mm2: 9.0; SizeZ_mm: 0.8; SizeX_mm: 2.0; SizeArea_mm2: 4.0; CompType: IC; AEC Qualified: N; AEC Category: Q200

## Sheet TIDA-00300_EVM_Hardware_Pg6.SchDoc: Hardware
size 431 x 279 mm; Date: Not shown in title block; ApprovedBy: Not shown in title block; CheckedBy: Not shown in title block; Author: Not shown in title block; CompanyName: Not shown in title block; DrawnBy: Sreenivasa; Engineer: Not shown in title block; Organization: Not shown in title block; Address1: Not shown in title block; Address2: Not shown in title block; Address3: Not shown in title block; Address4: Not shown in title block; DocumentNumber: 1; Revision: Use project parameter SCH_Rev; SheetNumber: 6; SheetTotal: 6; PageSetup: Record=PageOptions¦CenterHorizontal=True¦CenterVertical=True¦PrintScale=1.00¦XCorrection=1.00¦YCorrection=1.00¦PrintKind=0¦BorderSize=5000000¦LeftOffset=0¦BottomOffset=0¦Orientation=2¦PaperLength=1000¦PaperWidth=1000¦Scale=100¦PaperSource=15¦PrintQuality=600¦MediaType=1¦DitherType=10¦PaperKind=Letter¦PrintScaleMode=1
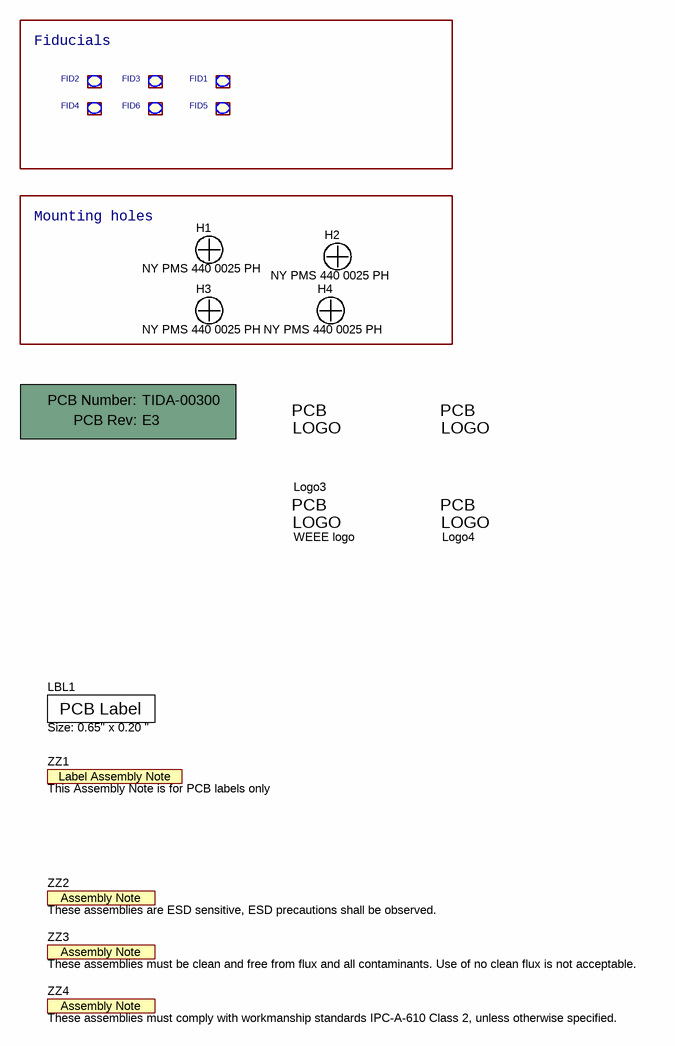
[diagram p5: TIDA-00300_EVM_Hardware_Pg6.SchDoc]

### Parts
!PCB  Printed Circuit Board  (value not drawn)  (mechanical)
FID1  Fiducial40_80  [FID_TOP_40_80BA]  (value not drawn)
FID2  Fiducial40_80  [FID_TOP_40_80BA]  (value not drawn)
FID3  Fiducial40_80  [FID_TOP_40_80BA]  (value not drawn)
FID4  Fiducial40_80  [FID_TOP_40_80BA]  (value not drawn)
FID5  Fiducial40_80  [FID_TOP_40_80BA]  (value not drawn)
FID6  Fiducial40_80  [FID_TOP_40_80BA]  (value not drawn)
H1  NY PMS 440 0025 PH  [NY PMS 440 0025 PH]
H2  NY PMS 440 0025 PH  [NY PMS 440 0025 PH]
H3  NY PMS 440 0025 PH  [NY PMS 440 0025 PH]
H4  NY PMS 440 0025 PH  [NY PMS 440 0025 PH]
LBL1  Size: 0.65" x 0.20 "  [Label_650x200]
Logo1  Pb-Free Symbol  [Pb-Free_Overlay_Small]  (value not drawn)  (no BOM)
Logo2  FCC disclaimer  [FCC_disclaimer]  (value not drawn)  (no BOM)
Logo3  WEEE logo  [WEEE_Minimum]  (no BOM)
Logo4  ESD Susceptible  [ESD_Overlay_small]  (value not drawn)  (no BOM)
ZZ1  This Assembly Note is for PCB labels only  [AssemblyNoteLabel]  (no BOM)
ZZ2  These assemblies are ESD sensitive, ESD precautions shall be observed.  [AssemblyNote]  (no BOM)
ZZ3  These assemblies must be clean and free from flux and all contaminants. Use of no clean flux is not acceptable.  [AssemblyNote]  (no BOM)
ZZ4  These assemblies must comply with workmanship standards IPC-A-610 Class 2, unless otherwise specified.  [AssemblyNote]  (no BOM)

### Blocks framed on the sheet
Fiducials: FID1-FID6
Mounting holes: H1-H4

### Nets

Not connected (* = marked no-connect by the designer): FID1 1; FID2 1; FID3 1; FID4 1; FID5 1; FID6 1

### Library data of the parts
!PCB = PCB: Manufacturer: Any; PartNumber: TIDA-00300; SymbolCreator: a0412235
FID1-FID6 = Fiducial40_0
H1-H4 = NY PMS 440 0025 PH: Machine Screw, Round, #4-40 x 1/4, Nylon, Philips panhead; Manufacturer: B&F Fastener Supply; CompType: Hardware; SymbolCreator: codlsc; U/M: EA
LBL1 = THT-14-423-10: Thermal Transfer Printable Labels, 0.650" W x 0.200" H - 10,000 per roll; Manufacturer: Brady; SymbolCreator: a0412235; CompType: Label
Logo1 = Pb-Free: SymbolCreator: a0412235
Logo2 = FCC_disclaimer: SymbolCreator: a0412235
Logo3 = CMP-0074769-1
Logo4 = ESD_Susceptible: ESD Susceptible Symbol; SymbolCreator: a0412235
ZZ1 = AssemblyNoteLabel: SymbolCreator: a0412235
ZZ2-ZZ4 = AssemblyNote: SymbolCreator: codlsc

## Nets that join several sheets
+5V_ISO: TIDA-00300_Isolated SPI, I2C & Fly buck Power Supply_Pg3  (14 pins), TIDA-00300_Isolated Power Supply +15V,-15V & +5V_Pg4  (6 pins)
+6V_ISO: TIDA-00300_Isolated SPI, I2C & Fly buck Power Supply_Pg3  (C22.1 D7.1 R36.1 TP8.1), TIDA-00300_Isolated Power Supply +15V,-15V & +5V_Pg4  (C29.1 C32.2 U5.5 U5.8)
+15V_ISO: TIDA-00300_Isolated SPI, I2C & Fly buck Power Supply_Pg3  (C33.2 C34.2 R34.1), TIDA-00300_Isolated Power Supply +15V,-15V & +5V_Pg4  (6 pins)
+18V_ISO: TIDA-00300_Isolated SPI, I2C & Fly buck Power Supply_Pg3  (C21.1 D9.1 TP7.1), TIDA-00300_Isolated Power Supply +15V,-15V & +5V_Pg4  (C23.1 U3.13 U3.15 U3.16)
-15V_ISO: TIDA-00300_Isolated SPI, I2C & Fly buck Power Supply_Pg3  (C24.1 C25.2 R35.1), TIDA-00300_Isolated Power Supply +15V,-15V & +5V_Pg4  (6 pins)
-18V_ISO: TIDA-00300_Isolated SPI, I2C & Fly buck Power Supply_Pg3  (C1.2 D2.2 TP1.1), TIDA-00300_Isolated Power Supply +15V,-15V & +5V_Pg4  (C5.1 C7.2 U1.5 U1.8)
GND_iso: TIDA-00300_Isolated SPI, I2C & Fly buck Power Supply_Pg3  (20 pins), TIDA-00300_Isolated Power Supply +15V,-15V & +5V_Pg4  (38 pins)

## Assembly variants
001: not fitted FID1 FID2 FID3 FID4 FID5 FID6 R9 R14 R15 R19 R37 R38 R39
